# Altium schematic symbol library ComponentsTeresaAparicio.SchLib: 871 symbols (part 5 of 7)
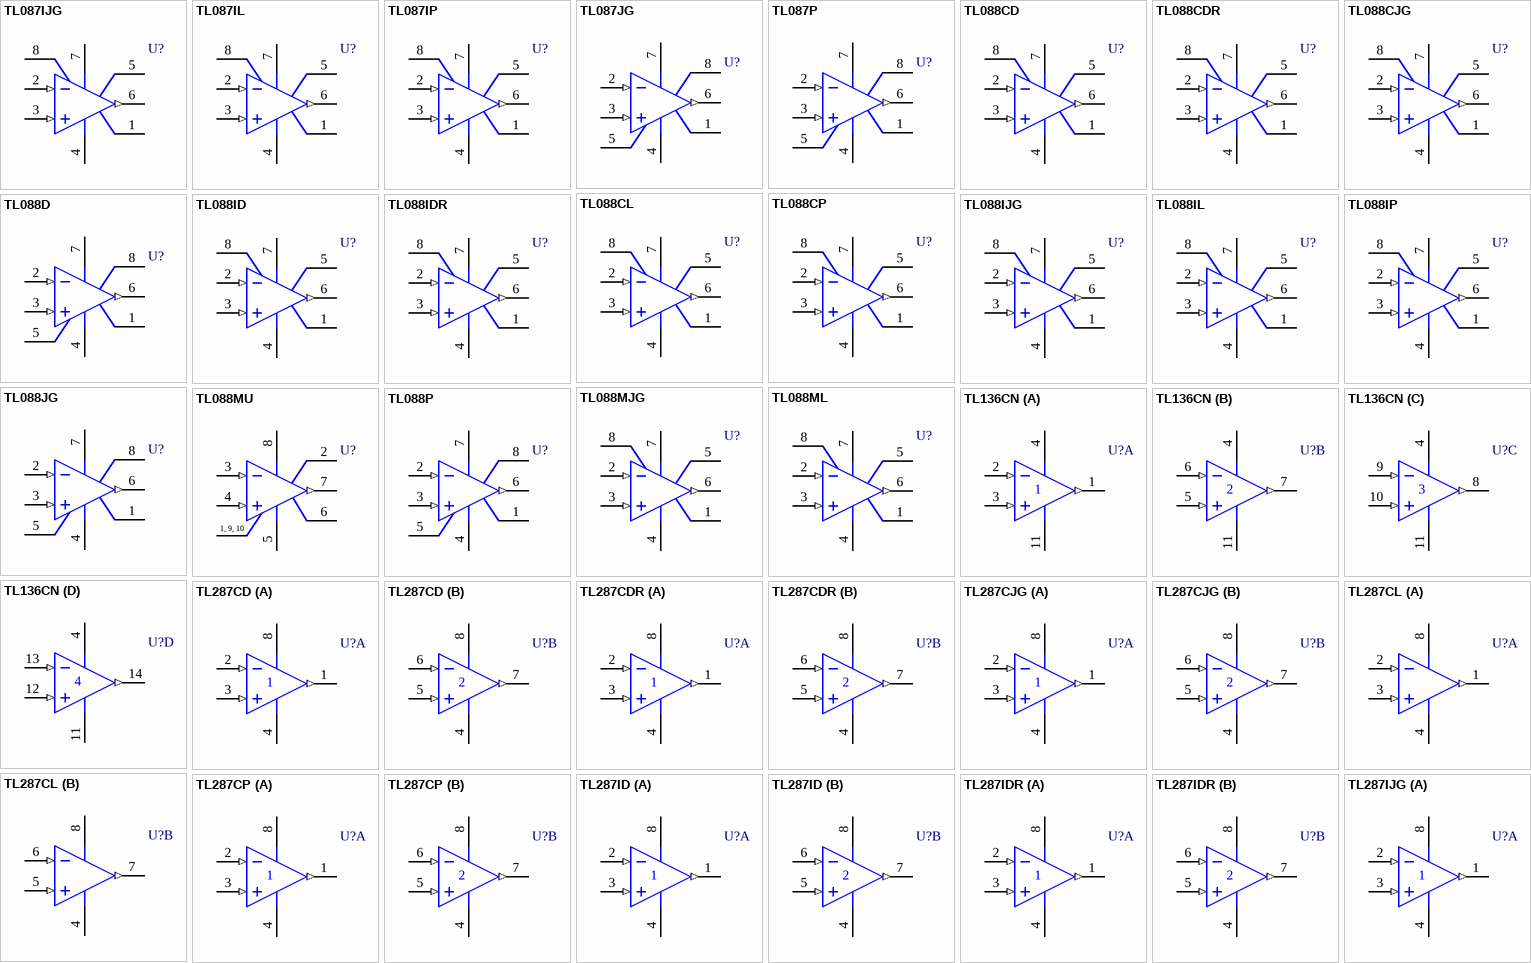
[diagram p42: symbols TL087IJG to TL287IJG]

## TL087IL
designator U?
JFET-Input Operational Amplifier; Note: Pin 4 is in electrical contact with the case; ComponentAvailability: Obsolete
footprint L008 (Can; 8 Leads; Pin Circle Dia. 5.08 mm; Lead Dia. 0.48 mm (max))
pins: 1 OS N1, 2 IN- (in), 3 IN+ (in), 4 V- (power), 5 OS N2, 6 OUT (out), 7 V+ (power), 8 NC

## TL087IP
designator U?
JFET-Input Operational Amplifier; ComponentAvailability: Obsolete
footprint P008 (DIP; 8 Leads; Row Spacing 7.62 mm; Pitch 2.54 mm)
3D model P008 (DIP; 8 Leads; Row Spacing 7.62 mm; Pitch 2.54 mm)
pins: 1 OS N1, 2 IN- (in), 3 IN+ (in), 4 V- (power), 5 OS N2, 6 OUT (out), 7 V+ (power), 8 NC

## TL087JG
designator U?
JFET-Input Operational Amplifier; Note: Pin 8 is not connected
footprint JG008 (DIP; 8 Leads; Row Spacing 7.62 mm; Pitch 2.54 mm)
3D model JG008 (DIP; 8 Leads; Row Spacing 7.62 mm; Pitch 2.54 mm)
simulation model TL087 (SUBCKT)
pins: 1 OS TRIM, 2 IN- (in), 3 IN+ (in), 4 V- (power), 5 OS TRIM, 6 OUT (out), 7 V+ (power), 8 NC

## TL087P
designator U?
JFET-Input Operational Amplifier; Note: Pin 8 is not connected
footprint P008 (DIP; 8 Leads; Row Spacing 7.62 mm; Pitch 2.54 mm)
3D model P008 (DIP; 8 Leads; Row Spacing 7.62 mm; Pitch 2.54 mm)
simulation model TL087 (SUBCKT)
pins: 1 OS TRIM, 2 IN- (in), 3 IN+ (in), 4 V- (power), 5 OS TRIM, 6 OUT (out), 7 V+ (power), 8 NC

## TL088CD
designator U?
JFET-Input Operational Amplifier; ComponentAvailability: Obsolete
footprint D008_L (SOIC, 8-Leads, Body 4.9x3.9mm, Pitch 1.27mm, IPC High Density)
footprint D008_M (SOIC, 8-Leads, Body 4.9x3.9mm, Pitch 1.27mm, IPC Low Density)
footprint D008_M (SOIC, 8-Leads, Body 4.9x3.9mm, Pitch 1.27mm, IPC Low Density)
3D model D008 (8-Pin Small Outline Integrated Circuit 1.27 mm Pitch)
pins: 1 OS N1, 2 IN- (in), 3 IN+ (in), 4 V- (power), 5 OS N2, 6 OUT (out), 7 V+ (power), 8 NC

## TL088CDR
designator U?
JFET-Input Operational Amplifier; ComponentAvailability: Obsolete
footprint D008_L (SOIC, 8-Leads, Body 4.9x3.9mm, Pitch 1.27mm, IPC High Density)
footprint D008_M (SOIC, 8-Leads, Body 4.9x3.9mm, Pitch 1.27mm, IPC Low Density)
footprint D008_M (SOIC, 8-Leads, Body 4.9x3.9mm, Pitch 1.27mm, IPC Low Density)
3D model D008 (8-Pin Small Outline Integrated Circuit 1.27 mm Pitch)
pins: 1 OS N1, 2 IN- (in), 3 IN+ (in), 4 V- (power), 5 OS N2, 6 OUT (out), 7 V+ (power), 8 NC

## TL088CJG
designator U?
JFET-Input Operational Amplifier; ComponentAvailability: Obsolete
footprint JG008 (DIP; 8 Leads; Row Spacing 7.62 mm; Pitch 2.54 mm)
3D model JG008 (DIP; 8 Leads; Row Spacing 7.62 mm; Pitch 2.54 mm)
pins: 1 OS N1, 2 IN- (in), 3 IN+ (in), 4 V- (power), 5 OS N2, 6 OUT (out), 7 V+ (power), 8 NC

## TL088CL
designator U?
JFET-Input Operational Amplifier; Note: Pin 4 is in electrical contact with the case; ComponentAvailability: Obsolete
footprint L008 (Can; 8 Leads; Pin Circle Dia. 5.08 mm; Lead Dia. 0.48 mm (max))
pins: 1 OS N1, 2 IN- (in), 3 IN+ (in), 4 V- (power), 5 OS N2, 6 OUT (out), 7 V+ (power), 8 NC

## TL088CP
designator U?
JFET-Input Operational Amplifier; ComponentAvailability: Obsolete
footprint P008 (DIP; 8 Leads; Row Spacing 7.62 mm; Pitch 2.54 mm)
3D model P008 (DIP; 8 Leads; Row Spacing 7.62 mm; Pitch 2.54 mm)
pins: 1 OS N1, 2 IN- (in), 3 IN+ (in), 4 V- (power), 5 OS N2, 6 OUT (out), 7 V+ (power), 8 NC

## TL088D
designator U?
JFET-Input Operational Amplifier; Note: Pin 8 is not connected
footprint D008_L (SOIC, 8-Leads, Body 4.9x3.9mm, Pitch 1.27mm, IPC High Density)
footprint D008_M (SOIC, 8-Leads, Body 4.9x3.9mm, Pitch 1.27mm, IPC Low Density)
footprint D008_M (SOIC, 8-Leads, Body 4.9x3.9mm, Pitch 1.27mm, IPC Low Density)
3D model D008 (8-Pin Small Outline Integrated Circuit 1.27 mm Pitch)
simulation model TL088 (SUBCKT)
pins: 1 OS TRIM, 2 IN- (in), 3 IN+ (in), 4 V- (power), 5 OS TRIM, 6 OUT (out), 7 V+ (power), 8 NC

## TL088ID
designator U?
JFET-Input Operational Amplifier; ComponentAvailability: Obsolete
footprint D008_L (SOIC, 8-Leads, Body 4.9x3.9mm, Pitch 1.27mm, IPC High Density)
footprint D008_M (SOIC, 8-Leads, Body 4.9x3.9mm, Pitch 1.27mm, IPC Low Density)
footprint D008_M (SOIC, 8-Leads, Body 4.9x3.9mm, Pitch 1.27mm, IPC Low Density)
3D model D008 (8-Pin Small Outline Integrated Circuit 1.27 mm Pitch)
pins: 1 OS N1, 2 IN- (in), 3 IN+ (in), 4 V- (power), 5 OS N2, 6 OUT (out), 7 V+ (power), 8 NC

## TL088IDR
designator U?
JFET-Input Operational Amplifier; ComponentAvailability: Obsolete
footprint D008_L (SOIC, 8-Leads, Body 4.9x3.9mm, Pitch 1.27mm, IPC High Density)
footprint D008_M (SOIC, 8-Leads, Body 4.9x3.9mm, Pitch 1.27mm, IPC Low Density)
footprint D008_M (SOIC, 8-Leads, Body 4.9x3.9mm, Pitch 1.27mm, IPC Low Density)
3D model D008 (8-Pin Small Outline Integrated Circuit 1.27 mm Pitch)
pins: 1 OS N1, 2 IN- (in), 3 IN+ (in), 4 V- (power), 5 OS N2, 6 OUT (out), 7 V+ (power), 8 NC

## TL088IJG
designator U?
JFET-Input Operational Amplifier; ComponentAvailability: Obsolete
footprint JG008 (DIP; 8 Leads; Row Spacing 7.62 mm; Pitch 2.54 mm)
3D model JG008 (DIP; 8 Leads; Row Spacing 7.62 mm; Pitch 2.54 mm)
pins: 1 OS N1, 2 IN- (in), 3 IN+ (in), 4 V- (power), 5 OS N2, 6 OUT (out), 7 V+ (power), 8 NC

## TL088IL
designator U?
JFET-Input Operational Amplifier; Note: Pin 4 is in electrical contact with the case; ComponentAvailability: Obsolete
footprint L008 (Can; 8 Leads; Pin Circle Dia. 5.08 mm; Lead Dia. 0.48 mm (max))
pins: 1 OS N1, 2 IN- (in), 3 IN+ (in), 4 V- (power), 5 OS N2, 6 OUT (out), 7 V+ (power), 8 NC

## TL088IP
designator U?
JFET-Input Operational Amplifier; ComponentAvailability: Obsolete
footprint P008 (DIP; 8 Leads; Row Spacing 7.62 mm; Pitch 2.54 mm)
3D model P008 (DIP; 8 Leads; Row Spacing 7.62 mm; Pitch 2.54 mm)
pins: 1 OS N1, 2 IN- (in), 3 IN+ (in), 4 V- (power), 5 OS N2, 6 OUT (out), 7 V+ (power), 8 NC

## TL088JG
designator U?
JFET-Input Operational Amplifier; Note: Pin 8 is not connected
footprint JG008 (DIP; 8 Leads; Row Spacing 7.62 mm; Pitch 2.54 mm)
3D model JG008 (DIP; 8 Leads; Row Spacing 7.62 mm; Pitch 2.54 mm)
simulation model TL088 (SUBCKT)
pins: 1 OS TRIM, 2 IN- (in), 3 IN+ (in), 4 V- (power), 5 OS TRIM, 6 OUT (out), 7 V+ (power), 8 NC

## TL088MJG
designator U?
JFET-Input Operational Amplifier; ComponentAvailability: Obsolete
footprint JG008 (DIP; 8 Leads; Row Spacing 7.62 mm; Pitch 2.54 mm)
3D model JG008 (DIP; 8 Leads; Row Spacing 7.62 mm; Pitch 2.54 mm)
pins: 1 OS N1, 2 IN- (in), 3 IN+ (in), 4 V- (power), 5 OS N2, 6 OUT (out), 7 V+ (power), 8 NC

## TL088ML
designator U?
JFET-Input Operational Amplifier; Note: Pin 4 is in electrical contact with the case; ComponentAvailability: Obsolete
footprint L008 (Can; 8 Leads; Pin Circle Dia. 5.08 mm; Lead Dia. 0.48 mm (max))
pins: 1 OS N1, 2 IN- (in), 3 IN+ (in), 4 V- (power), 5 OS N2, 6 OUT (out), 7 V+ (power), 8 NC

## TL088MU
designator U?
JFET-Input Operational Amplifier; ComponentAvailability: Obsolete
footprint U010 (DFP; 10 Leads; Body 7.1 x 6.4 mm (LxW max); Pitch 1.27 mm)
3D model U010 (DFP; 10 Leads; Body 7.1 x 6.4 mm (LxW max); Pitch 1.27 mm)
pins: 1 NC, 2 OS N1, 3 IN- (in), 4 IN+ (in), 5 V- (power), 6 OS N2, 7 OUT (out), 8 V+ (power), 9 NC, 10 NC

## TL088P
designator U?
JFET-Input Operational Amplifier; Note: Pin 8 is not connected
footprint P008 (DIP; 8 Leads; Row Spacing 7.62 mm; Pitch 2.54 mm)
3D model P008 (DIP; 8 Leads; Row Spacing 7.62 mm; Pitch 2.54 mm)
simulation model TL088 (SUBCKT)
pins: 1 OS TRIM, 2 IN- (in), 3 IN+ (in), 4 V- (power), 5 OS TRIM, 6 OUT (out), 7 V+ (power), 8 NC

## TL136CN
designator U?
Quad High-Performance Operational Amplifier
footprint N014 (DIP; 14 Leads; Row Spacing 7.62 mm; Pitch 2.54 mm)
3D model N014 (DIP; 14 Leads; Row Spacing 7.62 mm; Pitch 2.54 mm)
pins on every part: 4 V+ (power), 11 V- (power)
part A pins: 1 OUT (out), 2 IN- (in), 3 IN+ (in)
part B pins: 5 IN+ (in), 6 IN- (in), 7 OUT (out)
part C pins: 8 OUT (out), 9 IN- (in), 10 IN+ (in)
part D pins: 12 IN+ (in), 13 IN- (in), 14 OUT (out)

## TL287CD
designator U?
JFET-Input Operational Amplifier; ComponentAvailability: Obsolete
footprint D008_L (SOIC, 8-Leads, Body 4.9x3.9mm, Pitch 1.27mm, IPC High Density)
footprint D008_M (SOIC, 8-Leads, Body 4.9x3.9mm, Pitch 1.27mm, IPC Low Density)
footprint D008_M (SOIC, 8-Leads, Body 4.9x3.9mm, Pitch 1.27mm, IPC Low Density)
3D model D008 (8-Pin Small Outline Integrated Circuit 1.27 mm Pitch)
pins on every part: 4 V- (power), 8 V+ (power)
part A pins: 1 OUT (out), 2 IN- (in), 3 IN+ (in)
part B pins: 5 IN+ (in), 6 IN- (in), 7 OUT (out)

## TL287CDR
designator U?
JFET-Input Operational Amplifier; ComponentAvailability: Obsolete
footprint D008_L (SOIC, 8-Leads, Body 4.9x3.9mm, Pitch 1.27mm, IPC High Density)
footprint D008_M (SOIC, 8-Leads, Body 4.9x3.9mm, Pitch 1.27mm, IPC Low Density)
footprint D008_M (SOIC, 8-Leads, Body 4.9x3.9mm, Pitch 1.27mm, IPC Low Density)
3D model D008 (8-Pin Small Outline Integrated Circuit 1.27 mm Pitch)
pins on every part: 4 V- (power), 8 V+ (power)
part A pins: 1 OUT (out), 2 IN- (in), 3 IN+ (in)
part B pins: 5 IN+ (in), 6 IN- (in), 7 OUT (out)

## TL287CJG
designator U?
JFET-Input Operational Amplifier; ComponentAvailability: Obsolete
footprint JG008 (DIP; 8 Leads; Row Spacing 7.62 mm; Pitch 2.54 mm)
3D model JG008 (DIP; 8 Leads; Row Spacing 7.62 mm; Pitch 2.54 mm)
pins on every part: 4 V- (power), 8 V+ (power)
part A pins: 1 OUT (out), 2 IN- (in), 3 IN+ (in)
part B pins: 5 IN+ (in), 6 IN- (in), 7 OUT (out)

## TL287CL
designator U?
JFET-Input Operational Amplifier; Note: Pin 4 is in electrical contact with the case; ComponentAvailability: Obsolete
footprint L008 (Can; 8 Leads; Pin Circle Dia. 5.08 mm; Lead Dia. 0.48 mm (max))
pins on every part: 4 V- (power), 8 V+ (power)
part A pins: 1 OUT (out), 2 IN- (in), 3 IN+ (in)
part B pins: 5 IN+ (in), 6 IN- (in), 7 OUT (out)

## TL287CP
designator U?
JFET-Input Operational Amplifier; ComponentAvailability: Obsolete
footprint P008 (DIP; 8 Leads; Row Spacing 7.62 mm; Pitch 2.54 mm)
3D model P008 (DIP; 8 Leads; Row Spacing 7.62 mm; Pitch 2.54 mm)
pins on every part: 4 V- (power), 8 V+ (power)
part A pins: 1 OUT (out), 2 IN- (in), 3 IN+ (in)
part B pins: 5 IN+ (in), 6 IN- (in), 7 OUT (out)

## TL287ID
designator U?
JFET-Input Operational Amplifier; ComponentAvailability: Obsolete
footprint D008_L (SOIC, 8-Leads, Body 4.9x3.9mm, Pitch 1.27mm, IPC High Density)
footprint D008_M (SOIC, 8-Leads, Body 4.9x3.9mm, Pitch 1.27mm, IPC Low Density)
footprint D008_M (SOIC, 8-Leads, Body 4.9x3.9mm, Pitch 1.27mm, IPC Low Density)
3D model D008 (8-Pin Small Outline Integrated Circuit 1.27 mm Pitch)
pins on every part: 4 V- (power), 8 V+ (power)
part A pins: 1 OUT (out), 2 IN- (in), 3 IN+ (in)
part B pins: 5 IN+ (in), 6 IN- (in), 7 OUT (out)

## TL287IDR
designator U?
JFET-Input Operational Amplifier; ComponentAvailability: Obsolete
footprint D008_L (SOIC, 8-Leads, Body 4.9x3.9mm, Pitch 1.27mm, IPC High Density)
footprint D008_M (SOIC, 8-Leads, Body 4.9x3.9mm, Pitch 1.27mm, IPC Low Density)
footprint D008_M (SOIC, 8-Leads, Body 4.9x3.9mm, Pitch 1.27mm, IPC Low Density)
3D model D008 (8-Pin Small Outline Integrated Circuit 1.27 mm Pitch)
pins on every part: 4 V- (power), 8 V+ (power)
part A pins: 1 OUT (out), 2 IN- (in), 3 IN+ (in)
part B pins: 5 IN+ (in), 6 IN- (in), 7 OUT (out)

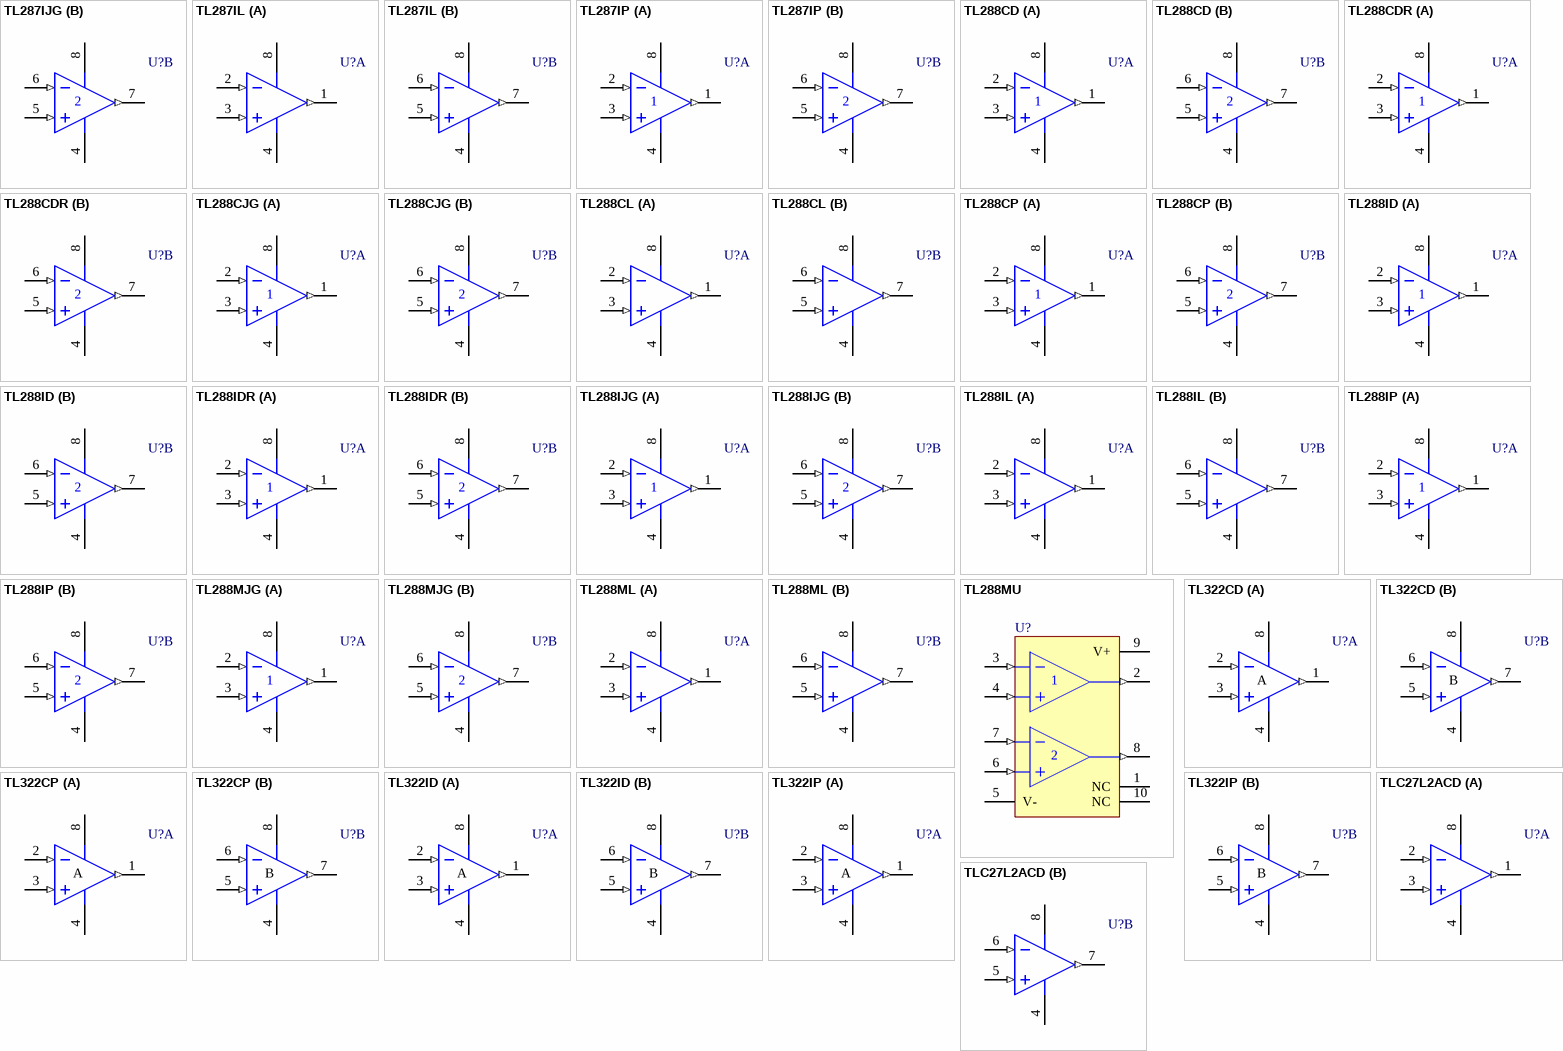
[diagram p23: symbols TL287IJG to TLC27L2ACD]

## TL287IJG
designator U?
JFET-Input Operational Amplifier; ComponentAvailability: Obsolete
footprint JG008 (DIP; 8 Leads; Row Spacing 7.62 mm; Pitch 2.54 mm)
3D model JG008 (DIP; 8 Leads; Row Spacing 7.62 mm; Pitch 2.54 mm)
pins on every part: 4 V- (power), 8 V+ (power)
part A pins: 1 OUT (out), 2 IN- (in), 3 IN+ (in)
part B pins: 5 IN+ (in), 6 IN- (in), 7 OUT (out)

## TL287IL
designator U?
JFET-Input Operational Amplifier; Note: Pin 4 is in electrical contact with the case; ComponentAvailability: Obsolete
footprint L008 (Can; 8 Leads; Pin Circle Dia. 5.08 mm; Lead Dia. 0.48 mm (max))
pins on every part: 4 V- (power), 8 V+ (power)
part A pins: 1 OUT (out), 2 IN- (in), 3 IN+ (in)
part B pins: 5 IN+ (in), 6 IN- (in), 7 OUT (out)

## TL287IP
designator U?
JFET-Input Operational Amplifier; ComponentAvailability: Obsolete
footprint P008 (DIP; 8 Leads; Row Spacing 7.62 mm; Pitch 2.54 mm)
3D model P008 (DIP; 8 Leads; Row Spacing 7.62 mm; Pitch 2.54 mm)
pins on every part: 4 V- (power), 8 V+ (power)
part A pins: 1 OUT (out), 2 IN- (in), 3 IN+ (in)
part B pins: 5 IN+ (in), 6 IN- (in), 7 OUT (out)

## TL288CD
designator U?
JFET-Input Operational Amplifier
footprint D008_L (SOIC, 8-Leads, Body 4.9x3.9mm, Pitch 1.27mm, IPC High Density)
footprint D008_M (SOIC, 8-Leads, Body 4.9x3.9mm, Pitch 1.27mm, IPC Low Density)
footprint D008_M (SOIC, 8-Leads, Body 4.9x3.9mm, Pitch 1.27mm, IPC Low Density)
3D model D008 (8-Pin Small Outline Integrated Circuit 1.27 mm Pitch)
pins on every part: 4 V- (power), 8 V+ (power)
part A pins: 1 OUT (out), 2 IN- (in), 3 IN+ (in)
part B pins: 5 IN+ (in), 6 IN- (in), 7 OUT (out)

## TL288CDR
designator U?
JFET-Input Operational Amplifier
footprint D008_L (SOIC, 8-Leads, Body 4.9x3.9mm, Pitch 1.27mm, IPC High Density)
footprint D008_M (SOIC, 8-Leads, Body 4.9x3.9mm, Pitch 1.27mm, IPC Low Density)
footprint D008_M (SOIC, 8-Leads, Body 4.9x3.9mm, Pitch 1.27mm, IPC Low Density)
3D model D008 (8-Pin Small Outline Integrated Circuit 1.27 mm Pitch)
pins on every part: 4 V- (power), 8 V+ (power)
part A pins: 1 OUT (out), 2 IN- (in), 3 IN+ (in)
part B pins: 5 IN+ (in), 6 IN- (in), 7 OUT (out)

## TL288CJG
designator U?
JFET-Input Operational Amplifier
footprint JG008 (DIP; 8 Leads; Row Spacing 7.62 mm; Pitch 2.54 mm)
3D model JG008 (DIP; 8 Leads; Row Spacing 7.62 mm; Pitch 2.54 mm)
pins on every part: 4 V- (power), 8 V+ (power)
part A pins: 1 OUT (out), 2 IN- (in), 3 IN+ (in)
part B pins: 5 IN+ (in), 6 IN- (in), 7 OUT (out)

## TL288CL
designator U?
JFET-Input Operational Amplifier; Note: Pin 4 is in electrical contact with the case
footprint L008 (Can; 8 Leads; Pin Circle Dia. 5.08 mm; Lead Dia. 0.48 mm (max))
pins on every part: 4 V- (power), 8 V+ (power)
part A pins: 1 OUT (out), 2 IN- (in), 3 IN+ (in)
part B pins: 5 IN+ (in), 6 IN- (in), 7 OUT (out)

## TL288CP
designator U?
JFET-Input Operational Amplifier
footprint P008 (DIP; 8 Leads; Row Spacing 7.62 mm; Pitch 2.54 mm)
3D model P008 (DIP; 8 Leads; Row Spacing 7.62 mm; Pitch 2.54 mm)
pins on every part: 4 V- (power), 8 V+ (power)
part A pins: 1 OUT (out), 2 IN- (in), 3 IN+ (in)
part B pins: 5 IN+ (in), 6 IN- (in), 7 OUT (out)

## TL288ID
designator U?
JFET-Input Operational Amplifier
footprint D008_L (SOIC, 8-Leads, Body 4.9x3.9mm, Pitch 1.27mm, IPC High Density)
footprint D008_M (SOIC, 8-Leads, Body 4.9x3.9mm, Pitch 1.27mm, IPC Low Density)
footprint D008_M (SOIC, 8-Leads, Body 4.9x3.9mm, Pitch 1.27mm, IPC Low Density)
3D model D008 (8-Pin Small Outline Integrated Circuit 1.27 mm Pitch)
pins on every part: 4 V- (power), 8 V+ (power)
part A pins: 1 OUT (out), 2 IN- (in), 3 IN+ (in)
part B pins: 5 IN+ (in), 6 IN- (in), 7 OUT (out)

## TL288IDR
designator U?
JFET-Input Operational Amplifier
footprint D008_L (SOIC, 8-Leads, Body 4.9x3.9mm, Pitch 1.27mm, IPC High Density)
footprint D008_M (SOIC, 8-Leads, Body 4.9x3.9mm, Pitch 1.27mm, IPC Low Density)
footprint D008_M (SOIC, 8-Leads, Body 4.9x3.9mm, Pitch 1.27mm, IPC Low Density)
3D model D008 (8-Pin Small Outline Integrated Circuit 1.27 mm Pitch)
pins on every part: 4 V- (power), 8 V+ (power)
part A pins: 1 OUT (out), 2 IN- (in), 3 IN+ (in)
part B pins: 5 IN+ (in), 6 IN- (in), 7 OUT (out)

## TL288IJG
designator U?
JFET-Input Operational Amplifier
footprint JG008 (DIP; 8 Leads; Row Spacing 7.62 mm; Pitch 2.54 mm)
3D model JG008 (DIP; 8 Leads; Row Spacing 7.62 mm; Pitch 2.54 mm)
pins on every part: 4 V- (power), 8 V+ (power)
part A pins: 1 OUT (out), 2 IN- (in), 3 IN+ (in)
part B pins: 5 IN+ (in), 6 IN- (in), 7 OUT (out)

## TL288IL
designator U?
JFET-Input Operational Amplifier; Note: Pin 4 is in electrical contact with the case
footprint L008 (Can; 8 Leads; Pin Circle Dia. 5.08 mm; Lead Dia. 0.48 mm (max))
pins on every part: 4 V- (power), 8 V+ (power)
part A pins: 1 OUT (out), 2 IN- (in), 3 IN+ (in)
part B pins: 5 IN+ (in), 6 IN- (in), 7 OUT (out)

## TL288IP
designator U?
JFET-Input Operational Amplifier
footprint P008 (DIP; 8 Leads; Row Spacing 7.62 mm; Pitch 2.54 mm)
3D model P008 (DIP; 8 Leads; Row Spacing 7.62 mm; Pitch 2.54 mm)
pins on every part: 4 V- (power), 8 V+ (power)
part A pins: 1 OUT (out), 2 IN- (in), 3 IN+ (in)
part B pins: 5 IN+ (in), 6 IN- (in), 7 OUT (out)

## TL288MJG
designator U?
JFET-Input Operational Amplifier
footprint JG008 (DIP; 8 Leads; Row Spacing 7.62 mm; Pitch 2.54 mm)
3D model JG008 (DIP; 8 Leads; Row Spacing 7.62 mm; Pitch 2.54 mm)
pins on every part: 4 V- (power), 8 V+ (power)
part A pins: 1 OUT (out), 2 IN- (in), 3 IN+ (in)
part B pins: 5 IN+ (in), 6 IN- (in), 7 OUT (out)

## TL288ML
designator U?
JFET-Input Operational Amplifier; Note: Pin 4 is in electrical contact with the case
footprint L008 (Can; 8 Leads; Pin Circle Dia. 5.08 mm; Lead Dia. 0.48 mm (max))
pins on every part: 4 V- (power), 8 V+ (power)
part A pins: 1 OUT (out), 2 IN- (in), 3 IN+ (in)
part B pins: 5 IN+ (in), 6 IN- (in), 7 OUT (out)

## TL288MU
designator U?
JFET-Input Operational Amplifier; ComponentAvailability: Obsolete
footprint U010 (DFP; 10 Leads; Body 7.1 x 6.4 mm (LxW max); Pitch 1.27 mm)
3D model U010 (DFP; 10 Leads; Body 7.1 x 6.4 mm (LxW max); Pitch 1.27 mm)
pins: 1 NC, 2 OUT (out), 3 IN- (in), 4 IN+ (in), 5 V- (power), 6 IN+ (in), 7 IN- (in), 8 OUT (out), 9 V+ (power), 10 NC

## TL322CD
designator U?
Dual Low-Power Operational Amplifier
footprint D008_L (SOIC, 8-Leads, Body 4.9x3.9mm, Pitch 1.27mm, IPC High Density)
footprint D008_M (SOIC, 8-Leads, Body 4.9x3.9mm, Pitch 1.27mm, IPC Low Density)
footprint D008_M (SOIC, 8-Leads, Body 4.9x3.9mm, Pitch 1.27mm, IPC Low Density)
3D model D008 (8-Pin Small Outline Integrated Circuit 1.27 mm Pitch)
simulation model TL322 (SUBCKT)
pins on every part: 4 V- (power), 8 V+ (power)
part A pins: 1 OUT (out), 2 IN- (in), 3 IN+ (in)
part B pins: 5 IN+ (in), 6 IN- (in), 7 OUT (out)

## TL322CP
designator U?
Dual Low-Power Operational Amplifier; ComponentAvailability: Obsolete
footprint P008 (DIP; 8 Leads; Row Spacing 7.62 mm; Pitch 2.54 mm)
3D model P008 (DIP; 8 Leads; Row Spacing 7.62 mm; Pitch 2.54 mm)
simulation model TL322 (SUBCKT)
pins on every part: 4 V- (power), 8 V+ (power)
part A pins: 1 OUT (out), 2 IN- (in), 3 IN+ (in)
part B pins: 5 IN+ (in), 6 IN- (in), 7 OUT (out)

## TL322ID
designator U?
Dual Low-Power Operational Amplifier; ComponentAvailability: Obsolete
footprint D008_L (SOIC, 8-Leads, Body 4.9x3.9mm, Pitch 1.27mm, IPC High Density)
footprint D008_M (SOIC, 8-Leads, Body 4.9x3.9mm, Pitch 1.27mm, IPC Low Density)
footprint D008_M (SOIC, 8-Leads, Body 4.9x3.9mm, Pitch 1.27mm, IPC Low Density)
3D model D008 (8-Pin Small Outline Integrated Circuit 1.27 mm Pitch)
simulation model TL322 (SUBCKT)
pins on every part: 4 V- (power), 8 V+ (power)
part A pins: 1 OUT (out), 2 IN- (in), 3 IN+ (in)
part B pins: 5 IN+ (in), 6 IN- (in), 7 OUT (out)

## TL322IP
designator U?
Dual Low-Power Operational Amplifier; ComponentAvailability: Obsolete
footprint P008 (DIP; 8 Leads; Row Spacing 7.62 mm; Pitch 2.54 mm)
3D model P008 (DIP; 8 Leads; Row Spacing 7.62 mm; Pitch 2.54 mm)
simulation model TL322 (SUBCKT)
pins on every part: 4 V- (power), 8 V+ (power)
part A pins: 1 OUT (out), 2 IN- (in), 3 IN+ (in)
part B pins: 5 IN+ (in), 6 IN- (in), 7 OUT (out)

## TLC27L2ACD
designator U?
LinCMOS Precision Dual Operational Amplifier
footprint D008_L (SOIC, 8-Leads, Body 4.9x3.9mm, Pitch 1.27mm, IPC High Density)
footprint D008_M (SOIC, 8-Leads, Body 4.9x3.9mm, Pitch 1.27mm, IPC Low Density)
footprint D008_M (SOIC, 8-Leads, Body 4.9x3.9mm, Pitch 1.27mm, IPC Low Density)
3D model D008 (8-Pin Small Outline Integrated Circuit 1.27 mm Pitch)
pins on every part: 4 GND (power), 8 VDD (power)
part A pins: 1 OUT (out), 2 IN- (in), 3 IN+ (in)
part B pins: 5 IN+ (in), 6 IN- (in), 7 OUT (out)

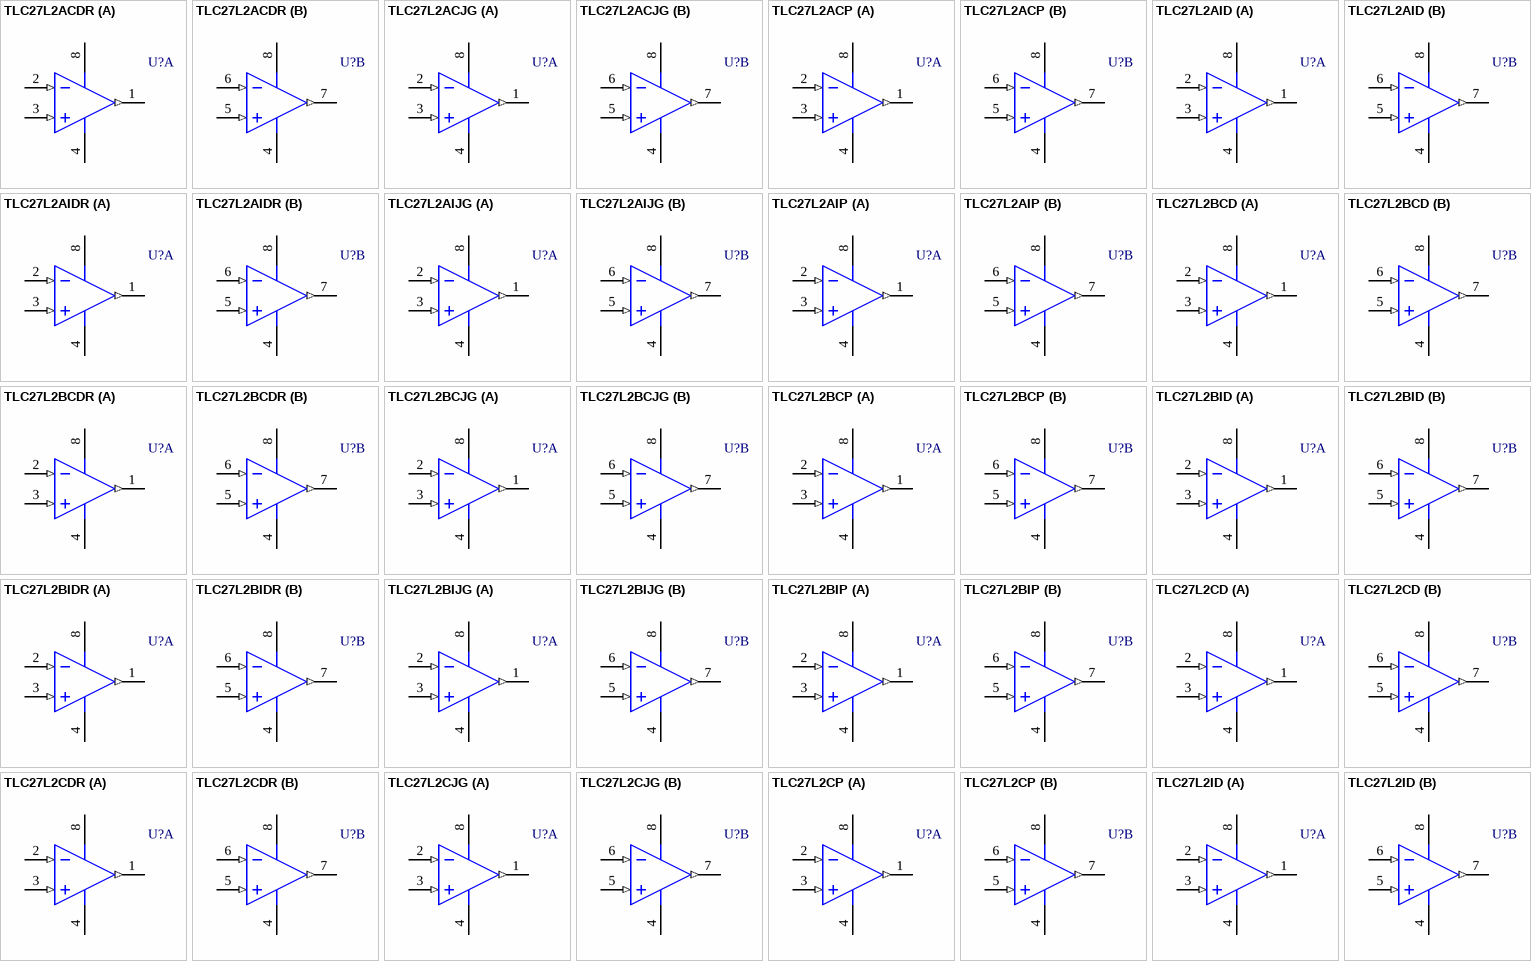
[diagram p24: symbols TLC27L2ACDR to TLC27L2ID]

## TLC27L2ACDR
designator U?
LinCMOS Precision Dual Operational Amplifier
footprint D008_L (SOIC, 8-Leads, Body 4.9x3.9mm, Pitch 1.27mm, IPC High Density)
footprint D008_M (SOIC, 8-Leads, Body 4.9x3.9mm, Pitch 1.27mm, IPC Low Density)
footprint D008_M (SOIC, 8-Leads, Body 4.9x3.9mm, Pitch 1.27mm, IPC Low Density)
3D model D008 (8-Pin Small Outline Integrated Circuit 1.27 mm Pitch)
pins on every part: 4 GND (power), 8 VDD (power)
part A pins: 1 OUT (out), 2 IN- (in), 3 IN+ (in)
part B pins: 5 IN+ (in), 6 IN- (in), 7 OUT (out)

## TLC27L2ACJG
designator U?
LinCMOS Precision Dual Operational Amplifier
footprint JG008 (DIP; 8 Leads; Row Spacing 7.62 mm; Pitch 2.54 mm)
3D model JG008 (DIP; 8 Leads; Row Spacing 7.62 mm; Pitch 2.54 mm)
pins on every part: 4 GND (power), 8 VDD (power)
part A pins: 1 OUT (out), 2 IN- (in), 3 IN+ (in)
part B pins: 5 IN+ (in), 6 IN- (in), 7 OUT (out)

## TLC27L2ACP
designator U?
LinCMOS Precision Dual Operational Amplifier
footprint P008 (DIP; 8 Leads; Row Spacing 7.62 mm; Pitch 2.54 mm)
3D model P008 (DIP; 8 Leads; Row Spacing 7.62 mm; Pitch 2.54 mm)
pins on every part: 4 GND (power), 8 VDD (power)
part A pins: 1 OUT (out), 2 IN- (in), 3 IN+ (in)
part B pins: 5 IN+ (in), 6 IN- (in), 7 OUT (out)

## TLC27L2AID
designator U?
LinCMOS Precision Dual Operational Amplifier
footprint D008_L (SOIC, 8-Leads, Body 4.9x3.9mm, Pitch 1.27mm, IPC High Density)
footprint D008_M (SOIC, 8-Leads, Body 4.9x3.9mm, Pitch 1.27mm, IPC Low Density)
footprint D008_M (SOIC, 8-Leads, Body 4.9x3.9mm, Pitch 1.27mm, IPC Low Density)
3D model D008 (8-Pin Small Outline Integrated Circuit 1.27 mm Pitch)
pins on every part: 4 GND (power), 8 VDD (power)
part A pins: 1 OUT (out), 2 IN- (in), 3 IN+ (in)
part B pins: 5 IN+ (in), 6 IN- (in), 7 OUT (out)

## TLC27L2AIDR
designator U?
LinCMOS Precision Dual Operational Amplifier
footprint D008_L (SOIC, 8-Leads, Body 4.9x3.9mm, Pitch 1.27mm, IPC High Density)
footprint D008_M (SOIC, 8-Leads, Body 4.9x3.9mm, Pitch 1.27mm, IPC Low Density)
footprint D008_M (SOIC, 8-Leads, Body 4.9x3.9mm, Pitch 1.27mm, IPC Low Density)
3D model D008 (8-Pin Small Outline Integrated Circuit 1.27 mm Pitch)
pins on every part: 4 GND (power), 8 VDD (power)
part A pins: 1 OUT (out), 2 IN- (in), 3 IN+ (in)
part B pins: 5 IN+ (in), 6 IN- (in), 7 OUT (out)

## TLC27L2AIJG
designator U?
LinCMOS Precision Dual Operational Amplifier
footprint JG008 (DIP; 8 Leads; Row Spacing 7.62 mm; Pitch 2.54 mm)
3D model JG008 (DIP; 8 Leads; Row Spacing 7.62 mm; Pitch 2.54 mm)
pins on every part: 4 GND (power), 8 VDD (power)
part A pins: 1 OUT (out), 2 IN- (in), 3 IN+ (in)
part B pins: 5 IN+ (in), 6 IN- (in), 7 OUT (out)

## TLC27L2AIP
designator U?
LinCMOS Precision Dual Operational Amplifier
footprint P008 (DIP; 8 Leads; Row Spacing 7.62 mm; Pitch 2.54 mm)
3D model P008 (DIP; 8 Leads; Row Spacing 7.62 mm; Pitch 2.54 mm)
pins on every part: 4 GND (power), 8 VDD (power)
part A pins: 1 OUT (out), 2 IN- (in), 3 IN+ (in)
part B pins: 5 IN+ (in), 6 IN- (in), 7 OUT (out)

## TLC27L2BCD
designator U?
LinCMOS Precision Dual Operational Amplifier
footprint D008_L (SOIC, 8-Leads, Body 4.9x3.9mm, Pitch 1.27mm, IPC High Density)
footprint D008_M (SOIC, 8-Leads, Body 4.9x3.9mm, Pitch 1.27mm, IPC Low Density)
footprint D008_M (SOIC, 8-Leads, Body 4.9x3.9mm, Pitch 1.27mm, IPC Low Density)
3D model D008 (8-Pin Small Outline Integrated Circuit 1.27 mm Pitch)
pins on every part: 4 GND (power), 8 VDD (power)
part A pins: 1 OUT (out), 2 IN- (in), 3 IN+ (in)
part B pins: 5 IN+ (in), 6 IN- (in), 7 OUT (out)

## TLC27L2BCDR
designator U?
LinCMOS Precision Dual Operational Amplifier
footprint D008_L (SOIC, 8-Leads, Body 4.9x3.9mm, Pitch 1.27mm, IPC High Density)
footprint D008_M (SOIC, 8-Leads, Body 4.9x3.9mm, Pitch 1.27mm, IPC Low Density)
footprint D008_M (SOIC, 8-Leads, Body 4.9x3.9mm, Pitch 1.27mm, IPC Low Density)
3D model D008 (8-Pin Small Outline Integrated Circuit 1.27 mm Pitch)
pins on every part: 4 GND (power), 8 VDD (power)
part A pins: 1 OUT (out), 2 IN- (in), 3 IN+ (in)
part B pins: 5 IN+ (in), 6 IN- (in), 7 OUT (out)

## TLC27L2BCJG
designator U?
LinCMOS Precision Dual Operational Amplifier
footprint JG008 (DIP; 8 Leads; Row Spacing 7.62 mm; Pitch 2.54 mm)
3D model JG008 (DIP; 8 Leads; Row Spacing 7.62 mm; Pitch 2.54 mm)
pins on every part: 4 GND (power), 8 VDD (power)
part A pins: 1 OUT (out), 2 IN- (in), 3 IN+ (in)
part B pins: 5 IN+ (in), 6 IN- (in), 7 OUT (out)

## TLC27L2BCP
designator U?
LinCMOS Precision Dual Operational Amplifier
footprint P008 (DIP; 8 Leads; Row Spacing 7.62 mm; Pitch 2.54 mm)
3D model P008 (DIP; 8 Leads; Row Spacing 7.62 mm; Pitch 2.54 mm)
pins on every part: 4 GND (power), 8 VDD (power)
part A pins: 1 OUT (out), 2 IN- (in), 3 IN+ (in)
part B pins: 5 IN+ (in), 6 IN- (in), 7 OUT (out)

## TLC27L2BID
designator U?
LinCMOS Precision Dual Operational Amplifier
footprint D008_L (SOIC, 8-Leads, Body 4.9x3.9mm, Pitch 1.27mm, IPC High Density)
footprint D008_M (SOIC, 8-Leads, Body 4.9x3.9mm, Pitch 1.27mm, IPC Low Density)
footprint D008_M (SOIC, 8-Leads, Body 4.9x3.9mm, Pitch 1.27mm, IPC Low Density)
3D model D008 (8-Pin Small Outline Integrated Circuit 1.27 mm Pitch)
pins on every part: 4 GND (power), 8 VDD (power)
part A pins: 1 OUT (out), 2 IN- (in), 3 IN+ (in)
part B pins: 5 IN+ (in), 6 IN- (in), 7 OUT (out)

## TLC27L2BIDR
designator U?
LinCMOS Precision Dual Operational Amplifier
footprint D008_L (SOIC, 8-Leads, Body 4.9x3.9mm, Pitch 1.27mm, IPC High Density)
footprint D008_M (SOIC, 8-Leads, Body 4.9x3.9mm, Pitch 1.27mm, IPC Low Density)
footprint D008_M (SOIC, 8-Leads, Body 4.9x3.9mm, Pitch 1.27mm, IPC Low Density)
3D model D008 (8-Pin Small Outline Integrated Circuit 1.27 mm Pitch)
pins on every part: 4 GND (power), 8 VDD (power)
part A pins: 1 OUT (out), 2 IN- (in), 3 IN+ (in)
part B pins: 5 IN+ (in), 6 IN- (in), 7 OUT (out)

## TLC27L2BIJG
designator U?
LinCMOS Precision Dual Operational Amplifier
footprint JG008 (DIP; 8 Leads; Row Spacing 7.62 mm; Pitch 2.54 mm)
3D model JG008 (DIP; 8 Leads; Row Spacing 7.62 mm; Pitch 2.54 mm)
pins on every part: 4 GND (power), 8 VDD (power)
part A pins: 1 OUT (out), 2 IN- (in), 3 IN+ (in)
part B pins: 5 IN+ (in), 6 IN- (in), 7 OUT (out)

## TLC27L2BIP
designator U?
LinCMOS Precision Dual Operational Amplifier
footprint P008 (DIP; 8 Leads; Row Spacing 7.62 mm; Pitch 2.54 mm)
3D model P008 (DIP; 8 Leads; Row Spacing 7.62 mm; Pitch 2.54 mm)
pins on every part: 4 GND (power), 8 VDD (power)
part A pins: 1 OUT (out), 2 IN- (in), 3 IN+ (in)
part B pins: 5 IN+ (in), 6 IN- (in), 7 OUT (out)

## TLC27L2CD
designator U?
LinCMOS Precision Dual Operational Amplifier
footprint D008_L (SOIC, 8-Leads, Body 4.9x3.9mm, Pitch 1.27mm, IPC High Density)
footprint D008_M (SOIC, 8-Leads, Body 4.9x3.9mm, Pitch 1.27mm, IPC Low Density)
footprint D008_M (SOIC, 8-Leads, Body 4.9x3.9mm, Pitch 1.27mm, IPC Low Density)
3D model D008 (8-Pin Small Outline Integrated Circuit 1.27 mm Pitch)
pins on every part: 4 GND (power), 8 VDD (power)
part A pins: 1 OUT (out), 2 IN- (in), 3 IN+ (in)
part B pins: 5 IN+ (in), 6 IN- (in), 7 OUT (out)

## TLC27L2CDR
designator U?
LinCMOS Precision Dual Operational Amplifier
footprint D008_L (SOIC, 8-Leads, Body 4.9x3.9mm, Pitch 1.27mm, IPC High Density)
footprint D008_M (SOIC, 8-Leads, Body 4.9x3.9mm, Pitch 1.27mm, IPC Low Density)
footprint D008_M (SOIC, 8-Leads, Body 4.9x3.9mm, Pitch 1.27mm, IPC Low Density)
3D model D008 (8-Pin Small Outline Integrated Circuit 1.27 mm Pitch)
pins on every part: 4 GND (power), 8 VDD (power)
part A pins: 1 OUT (out), 2 IN- (in), 3 IN+ (in)
part B pins: 5 IN+ (in), 6 IN- (in), 7 OUT (out)

## TLC27L2CJG
designator U?
LinCMOS Precision Dual Operational Amplifier
footprint JG008 (DIP; 8 Leads; Row Spacing 7.62 mm; Pitch 2.54 mm)
3D model JG008 (DIP; 8 Leads; Row Spacing 7.62 mm; Pitch 2.54 mm)
pins on every part: 4 GND (power), 8 VDD (power)
part A pins: 1 OUT (out), 2 IN- (in), 3 IN+ (in)
part B pins: 5 IN+ (in), 6 IN- (in), 7 OUT (out)

## TLC27L2CP
designator U?
LinCMOS Precision Dual Operational Amplifier
footprint P008 (DIP; 8 Leads; Row Spacing 7.62 mm; Pitch 2.54 mm)
3D model P008 (DIP; 8 Leads; Row Spacing 7.62 mm; Pitch 2.54 mm)
pins on every part: 4 GND (power), 8 VDD (power)
part A pins: 1 OUT (out), 2 IN- (in), 3 IN+ (in)
part B pins: 5 IN+ (in), 6 IN- (in), 7 OUT (out)

## TLC27L2ID
designator U?
LinCMOS Precision Dual Operational Amplifier
footprint D008_L (SOIC, 8-Leads, Body 4.9x3.9mm, Pitch 1.27mm, IPC High Density)
footprint D008_M (SOIC, 8-Leads, Body 4.9x3.9mm, Pitch 1.27mm, IPC Low Density)
footprint D008_M (SOIC, 8-Leads, Body 4.9x3.9mm, Pitch 1.27mm, IPC Low Density)
3D model D008 (8-Pin Small Outline Integrated Circuit 1.27 mm Pitch)
pins on every part: 4 GND (power), 8 VDD (power)
part A pins: 1 OUT (out), 2 IN- (in), 3 IN+ (in)
part B pins: 5 IN+ (in), 6 IN- (in), 7 OUT (out)

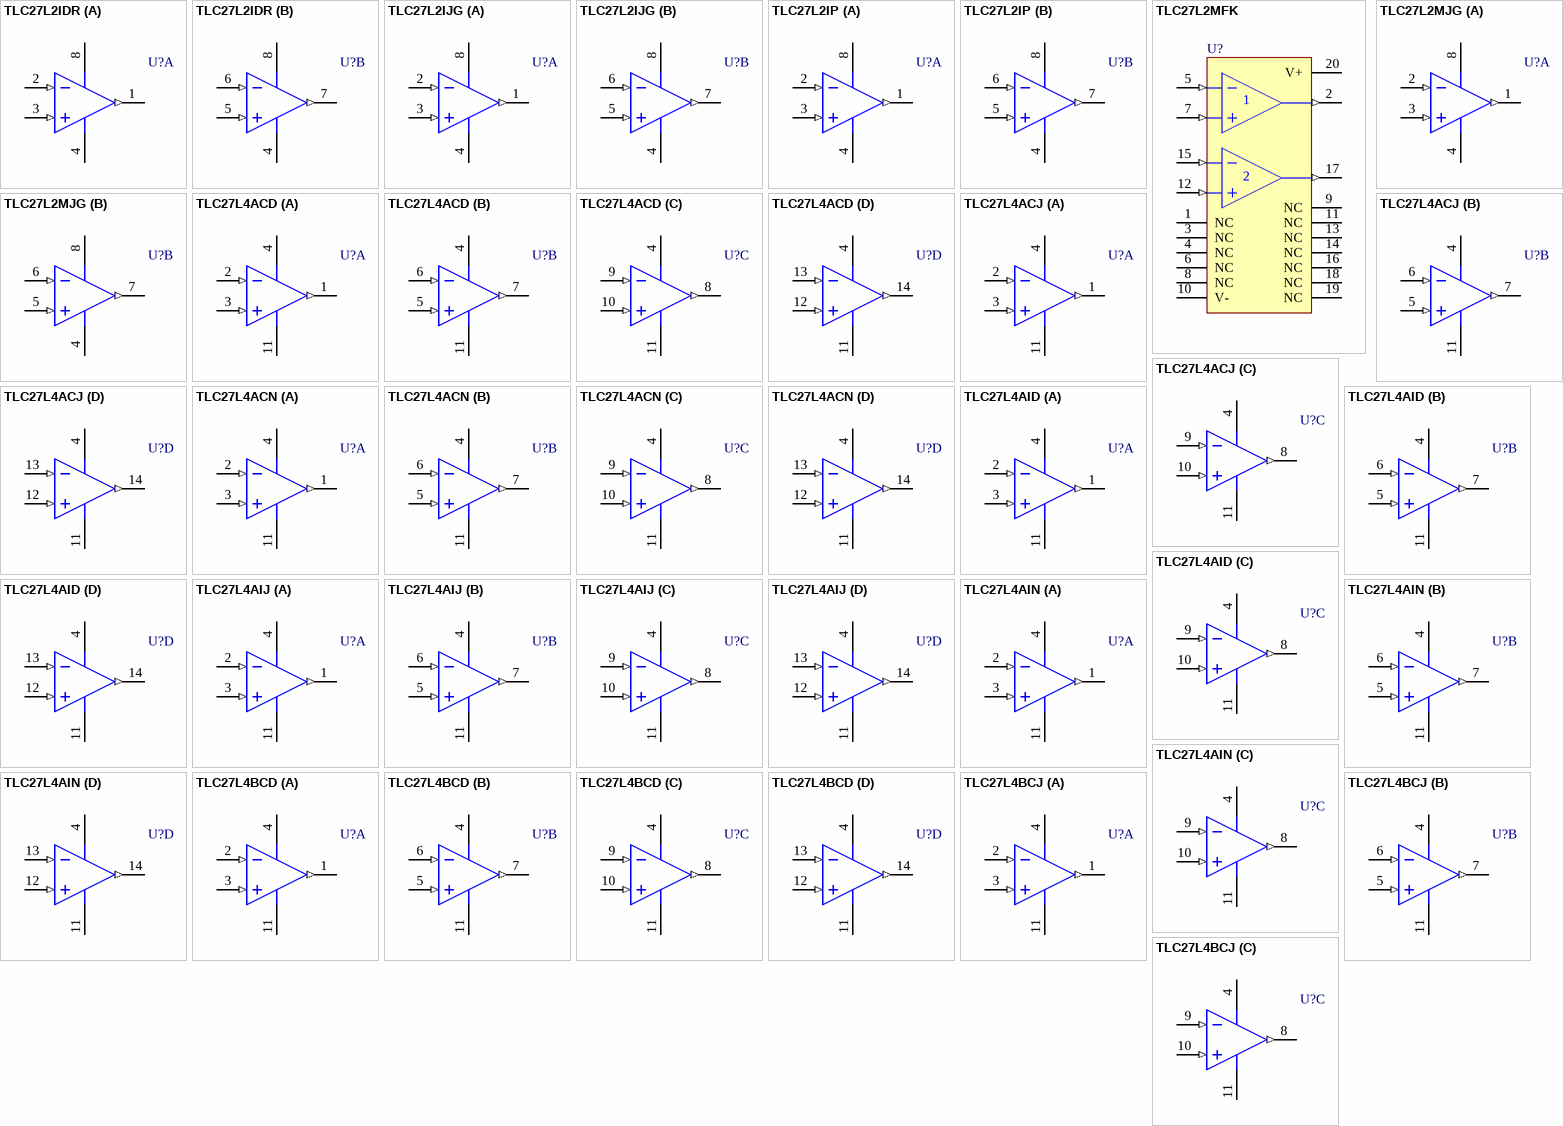
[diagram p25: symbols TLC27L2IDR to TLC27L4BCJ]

## TLC27L2IDR
designator U?
LinCMOS Precision Dual Operational Amplifier
footprint D008_L (SOIC, 8-Leads, Body 4.9x3.9mm, Pitch 1.27mm, IPC High Density)
footprint D008_M (SOIC, 8-Leads, Body 4.9x3.9mm, Pitch 1.27mm, IPC Low Density)
footprint D008_M (SOIC, 8-Leads, Body 4.9x3.9mm, Pitch 1.27mm, IPC Low Density)
3D model D008 (8-Pin Small Outline Integrated Circuit 1.27 mm Pitch)
pins on every part: 4 GND (power), 8 VDD (power)
part A pins: 1 OUT (out), 2 IN- (in), 3 IN+ (in)
part B pins: 5 IN+ (in), 6 IN- (in), 7 OUT (out)

## TLC27L2IJG
designator U?
LinCMOS Precision Dual Operational Amplifier
footprint JG008 (DIP; 8 Leads; Row Spacing 7.62 mm; Pitch 2.54 mm)
3D model JG008 (DIP; 8 Leads; Row Spacing 7.62 mm; Pitch 2.54 mm)
pins on every part: 4 GND (power), 8 VDD (power)
part A pins: 1 OUT (out), 2 IN- (in), 3 IN+ (in)
part B pins: 5 IN+ (in), 6 IN- (in), 7 OUT (out)

## TLC27L2IP
designator U?
LinCMOS Precision Dual Operational Amplifier
footprint P008 (DIP; 8 Leads; Row Spacing 7.62 mm; Pitch 2.54 mm)
3D model P008 (DIP; 8 Leads; Row Spacing 7.62 mm; Pitch 2.54 mm)
pins on every part: 4 GND (power), 8 VDD (power)
part A pins: 1 OUT (out), 2 IN- (in), 3 IN+ (in)
part B pins: 5 IN+ (in), 6 IN- (in), 7 OUT (out)

## TLC27L2MFK
designator U?
LinCMOS Precision Dual Operational Amplifier; ComponentAvailability: Obsolete
footprint FK020 (Leadless Chip Carrier; 20 Terminals; Body 8.9 x 8.9 mm)
pins: 1 NC, 2 OUT (out), 3 NC, 4 NC, 5 IN- (in), 6 NC, 7 IN+ (in), 8 NC, 9 NC, 10 V- (power), 11 NC, 12 IN+ (in), 13 NC, 14 NC, 15 IN- (in), 16 NC, 17 OUT (out), 18 NC, 19 NC, 20 V+ (power)

## TLC27L2MJG
designator U?
LinCMOS Precision Dual Operational Amplifier; ComponentAvailability: Obsolete
footprint JG008 (DIP; 8 Leads; Row Spacing 7.62 mm; Pitch 2.54 mm)
3D model JG008 (DIP; 8 Leads; Row Spacing 7.62 mm; Pitch 2.54 mm)
pins on every part: 4 GND (power), 8 VDD (power)
part A pins: 1 OUT (out), 2 IN- (in), 3 IN+ (in)
part B pins: 5 IN+ (in), 6 IN- (in), 7 OUT (out)

## TLC27L4ACD
designator U?
LinCMOS Precision Quad Operational Amplifier
footprint D014_N (SOIC, 14-Leads, Body 8.7x3.9mm, Pitch 1.27mm, IPC Medium Density)
footprint D014_L (SOIC, 14-Leads, Body 8.7x3.9mm, Pitch 1.27mm, IPC High Density)
footprint D014_M (SOIC, 14-Leads, Body 8.7x3.9mm, Pitch 1.27mm, IPC Low Density)
3D model D014 (14-Pin Small Outline Integrated Circuit 1.27 mm Pitch)
pins on every part: 4 V+ (power), 11 V- (power)
part A pins: 1 OUT (out), 2 IN- (in), 3 IN+ (in)
part B pins: 5 IN+ (in), 6 IN- (in), 7 OUT (out)
part C pins: 8 OUT (out), 9 IN- (in), 10 IN+ (in)
part D pins: 12 IN+ (in), 13 IN- (in), 14 OUT (out)

## TLC27L4ACJ
designator U?
LinCMOS Precision Quad Operational Amplifier
footprint J014 (DIP; 14 Leads; Row Spacing 7.62 mm; Pitch 2.54 mm)
3D model J014 (DIP; 14 Leads; Row Spacing 7.62 mm; Pitch 2.54 mm)
pins on every part: 4 V+ (power), 11 V- (power)
part A pins: 1 OUT (out), 2 IN- (in), 3 IN+ (in)
part B pins: 5 IN+ (in), 6 IN- (in), 7 OUT (out)
part C pins: 8 OUT (out), 9 IN- (in), 10 IN+ (in)
part D pins: 12 IN+ (in), 13 IN- (in), 14 OUT (out)

## TLC27L4ACN
designator U?
LinCMOS Precision Quad Operational Amplifier
footprint N014 (DIP; 14 Leads; Row Spacing 7.62 mm; Pitch 2.54 mm)
3D model N014 (DIP; 14 Leads; Row Spacing 7.62 mm; Pitch 2.54 mm)
pins on every part: 4 V+ (power), 11 V- (power)
part A pins: 1 OUT (out), 2 IN- (in), 3 IN+ (in)
part B pins: 5 IN+ (in), 6 IN- (in), 7 OUT (out)
part C pins: 8 OUT (out), 9 IN- (in), 10 IN+ (in)
part D pins: 12 IN+ (in), 13 IN- (in), 14 OUT (out)

## TLC27L4AID
designator U?
LinCMOS Precision Quad Operational Amplifier
footprint D014_N (SOIC, 14-Leads, Body 8.7x3.9mm, Pitch 1.27mm, IPC Medium Density)
footprint D014_L (SOIC, 14-Leads, Body 8.7x3.9mm, Pitch 1.27mm, IPC High Density)
footprint D014_M (SOIC, 14-Leads, Body 8.7x3.9mm, Pitch 1.27mm, IPC Low Density)
3D model D014 (14-Pin Small Outline Integrated Circuit 1.27 mm Pitch)
pins on every part: 4 V+ (power), 11 V- (power)
part A pins: 1 OUT (out), 2 IN- (in), 3 IN+ (in)
part B pins: 5 IN+ (in), 6 IN- (in), 7 OUT (out)
part C pins: 8 OUT (out), 9 IN- (in), 10 IN+ (in)
part D pins: 12 IN+ (in), 13 IN- (in), 14 OUT (out)

## TLC27L4AIJ
designator U?
LinCMOS Precision Quad Operational Amplifier
footprint J014 (DIP; 14 Leads; Row Spacing 7.62 mm; Pitch 2.54 mm)
3D model J014 (DIP; 14 Leads; Row Spacing 7.62 mm; Pitch 2.54 mm)
pins on every part: 4 V+ (power), 11 V- (power)
part A pins: 1 OUT (out), 2 IN- (in), 3 IN+ (in)
part B pins: 5 IN+ (in), 6 IN- (in), 7 OUT (out)
part C pins: 8 OUT (out), 9 IN- (in), 10 IN+ (in)
part D pins: 12 IN+ (in), 13 IN- (in), 14 OUT (out)

## TLC27L4AIN
designator U?
LinCMOS Precision Quad Operational Amplifier
footprint N014 (DIP; 14 Leads; Row Spacing 7.62 mm; Pitch 2.54 mm)
3D model N014 (DIP; 14 Leads; Row Spacing 7.62 mm; Pitch 2.54 mm)
pins on every part: 4 V+ (power), 11 V- (power)
part A pins: 1 OUT (out), 2 IN- (in), 3 IN+ (in)
part B pins: 5 IN+ (in), 6 IN- (in), 7 OUT (out)
part C pins: 8 OUT (out), 9 IN- (in), 10 IN+ (in)
part D pins: 12 IN+ (in), 13 IN- (in), 14 OUT (out)

## TLC27L4BCD
designator U?
LinCMOS Precision Quad Operational Amplifier
footprint D014_N (SOIC, 14-Leads, Body 8.7x3.9mm, Pitch 1.27mm, IPC Medium Density)
footprint D014_L (SOIC, 14-Leads, Body 8.7x3.9mm, Pitch 1.27mm, IPC High Density)
footprint D014_M (SOIC, 14-Leads, Body 8.7x3.9mm, Pitch 1.27mm, IPC Low Density)
3D model D014 (14-Pin Small Outline Integrated Circuit 1.27 mm Pitch)
pins on every part: 4 V+ (power), 11 V- (power)
part A pins: 1 OUT (out), 2 IN- (in), 3 IN+ (in)
part B pins: 5 IN+ (in), 6 IN- (in), 7 OUT (out)
part C pins: 8 OUT (out), 9 IN- (in), 10 IN+ (in)
part D pins: 12 IN+ (in), 13 IN- (in), 14 OUT (out)

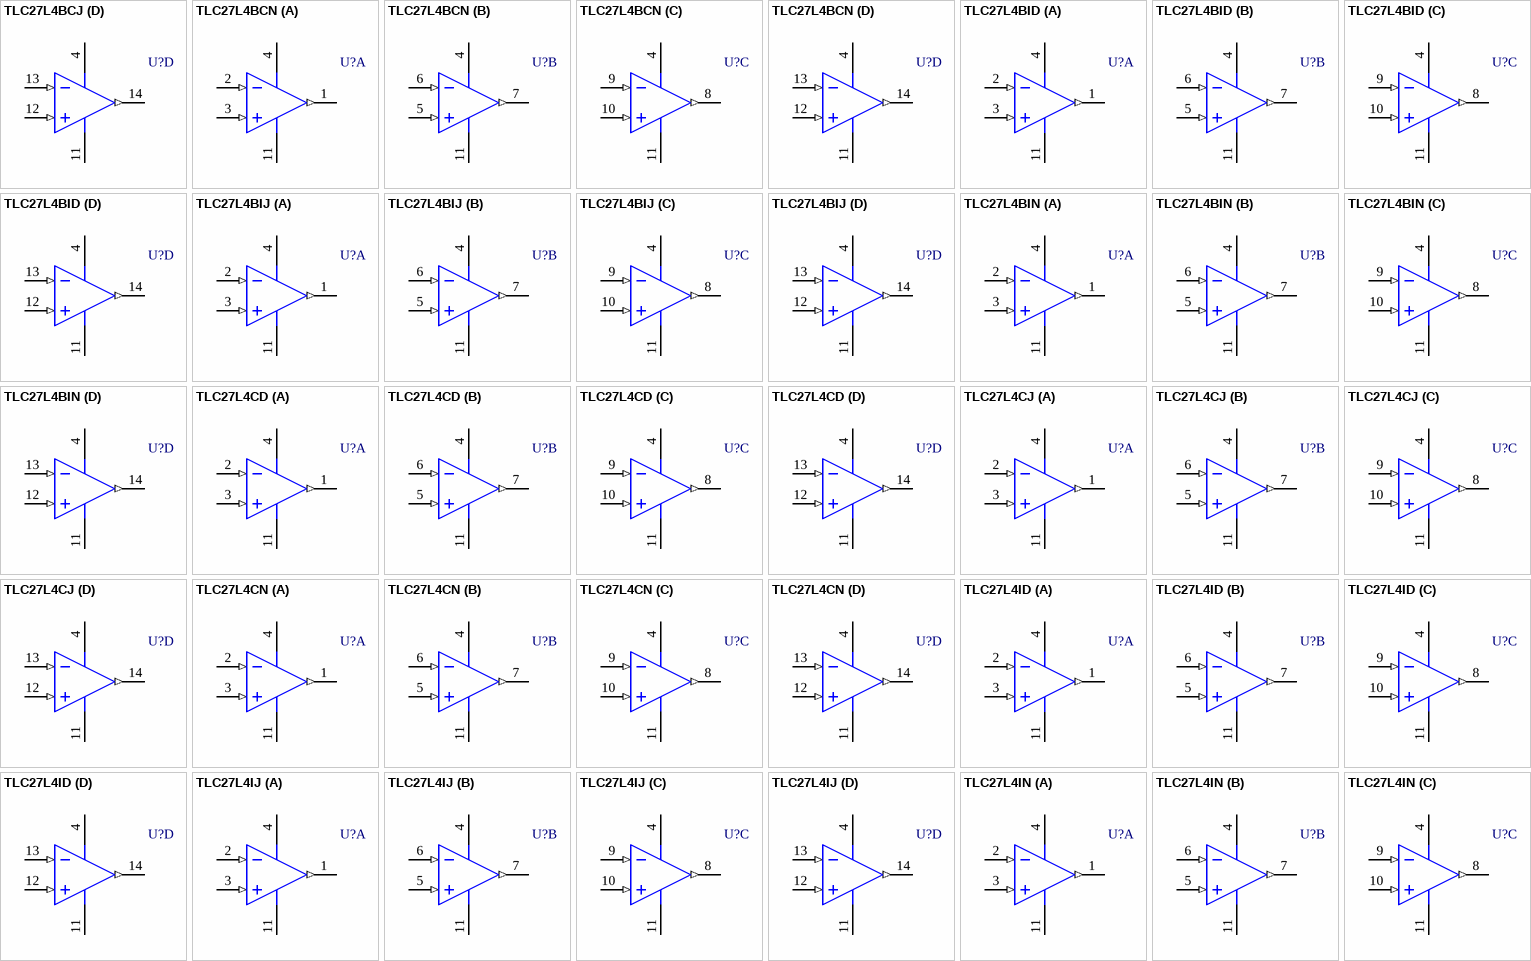
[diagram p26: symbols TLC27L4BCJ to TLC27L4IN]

## TLC27L4BCJ
designator U?
LinCMOS Precision Quad Operational Amplifier
footprint J014 (DIP; 14 Leads; Row Spacing 7.62 mm; Pitch 2.54 mm)
3D model J014 (DIP; 14 Leads; Row Spacing 7.62 mm; Pitch 2.54 mm)
pins on every part: 4 V+ (power), 11 V- (power)
part A pins: 1 OUT (out), 2 IN- (in), 3 IN+ (in)
part B pins: 5 IN+ (in), 6 IN- (in), 7 OUT (out)
part C pins: 8 OUT (out), 9 IN- (in), 10 IN+ (in)
part D pins: 12 IN+ (in), 13 IN- (in), 14 OUT (out)

## TLC27L4BCN
designator U?
LinCMOS Precision Quad Operational Amplifier
footprint N014 (DIP; 14 Leads; Row Spacing 7.62 mm; Pitch 2.54 mm)
3D model N014 (DIP; 14 Leads; Row Spacing 7.62 mm; Pitch 2.54 mm)
pins on every part: 4 V+ (power), 11 V- (power)
part A pins: 1 OUT (out), 2 IN- (in), 3 IN+ (in)
part B pins: 5 IN+ (in), 6 IN- (in), 7 OUT (out)
part C pins: 8 OUT (out), 9 IN- (in), 10 IN+ (in)
part D pins: 12 IN+ (in), 13 IN- (in), 14 OUT (out)

## TLC27L4BID
designator U?
LinCMOS Precision Quad Operational Amplifier
footprint D014_N (SOIC, 14-Leads, Body 8.7x3.9mm, Pitch 1.27mm, IPC Medium Density)
footprint D014_L (SOIC, 14-Leads, Body 8.7x3.9mm, Pitch 1.27mm, IPC High Density)
footprint D014_M (SOIC, 14-Leads, Body 8.7x3.9mm, Pitch 1.27mm, IPC Low Density)
3D model D014 (14-Pin Small Outline Integrated Circuit 1.27 mm Pitch)
pins on every part: 4 V+ (power), 11 V- (power)
part A pins: 1 OUT (out), 2 IN- (in), 3 IN+ (in)
part B pins: 5 IN+ (in), 6 IN- (in), 7 OUT (out)
part C pins: 8 OUT (out), 9 IN- (in), 10 IN+ (in)
part D pins: 12 IN+ (in), 13 IN- (in), 14 OUT (out)

## TLC27L4BIJ
designator U?
LinCMOS Precision Quad Operational Amplifier
footprint J014 (DIP; 14 Leads; Row Spacing 7.62 mm; Pitch 2.54 mm)
3D model J014 (DIP; 14 Leads; Row Spacing 7.62 mm; Pitch 2.54 mm)
pins on every part: 4 V+ (power), 11 V- (power)
part A pins: 1 OUT (out), 2 IN- (in), 3 IN+ (in)
part B pins: 5 IN+ (in), 6 IN- (in), 7 OUT (out)
part C pins: 8 OUT (out), 9 IN- (in), 10 IN+ (in)
part D pins: 12 IN+ (in), 13 IN- (in), 14 OUT (out)

## TLC27L4BIN
designator U?
LinCMOS Precision Quad Operational Amplifier
footprint N014 (DIP; 14 Leads; Row Spacing 7.62 mm; Pitch 2.54 mm)
3D model N014 (DIP; 14 Leads; Row Spacing 7.62 mm; Pitch 2.54 mm)
pins on every part: 4 V+ (power), 11 V- (power)
part A pins: 1 OUT (out), 2 IN- (in), 3 IN+ (in)
part B pins: 5 IN+ (in), 6 IN- (in), 7 OUT (out)
part C pins: 8 OUT (out), 9 IN- (in), 10 IN+ (in)
part D pins: 12 IN+ (in), 13 IN- (in), 14 OUT (out)

## TLC27L4CD
designator U?
LinCMOS Precision Quad Operational Amplifier
footprint D014_N (SOIC, 14-Leads, Body 8.7x3.9mm, Pitch 1.27mm, IPC Medium Density)
footprint D014_L (SOIC, 14-Leads, Body 8.7x3.9mm, Pitch 1.27mm, IPC High Density)
footprint D014_M (SOIC, 14-Leads, Body 8.7x3.9mm, Pitch 1.27mm, IPC Low Density)
3D model D014 (14-Pin Small Outline Integrated Circuit 1.27 mm Pitch)
pins on every part: 4 V+ (power), 11 V- (power)
part A pins: 1 OUT (out), 2 IN- (in), 3 IN+ (in)
part B pins: 5 IN+ (in), 6 IN- (in), 7 OUT (out)
part C pins: 8 OUT (out), 9 IN- (in), 10 IN+ (in)
part D pins: 12 IN+ (in), 13 IN- (in), 14 OUT (out)

## TLC27L4CJ
designator U?
LinCMOS Precision Quad Operational Amplifier
footprint J014 (DIP; 14 Leads; Row Spacing 7.62 mm; Pitch 2.54 mm)
3D model J014 (DIP; 14 Leads; Row Spacing 7.62 mm; Pitch 2.54 mm)
pins on every part: 4 V+ (power), 11 V- (power)
part A pins: 1 OUT (out), 2 IN- (in), 3 IN+ (in)
part B pins: 5 IN+ (in), 6 IN- (in), 7 OUT (out)
part C pins: 8 OUT (out), 9 IN- (in), 10 IN+ (in)
part D pins: 12 IN+ (in), 13 IN- (in), 14 OUT (out)

## TLC27L4CN
designator U?
LinCMOS Precision Quad Operational Amplifier
footprint N014 (DIP; 14 Leads; Row Spacing 7.62 mm; Pitch 2.54 mm)
3D model N014 (DIP; 14 Leads; Row Spacing 7.62 mm; Pitch 2.54 mm)
pins on every part: 4 V+ (power), 11 V- (power)
part A pins: 1 OUT (out), 2 IN- (in), 3 IN+ (in)
part B pins: 5 IN+ (in), 6 IN- (in), 7 OUT (out)
part C pins: 8 OUT (out), 9 IN- (in), 10 IN+ (in)
part D pins: 12 IN+ (in), 13 IN- (in), 14 OUT (out)

## TLC27L4ID
designator U?
LinCMOS Precision Quad Operational Amplifier
footprint D014_N (SOIC, 14-Leads, Body 8.7x3.9mm, Pitch 1.27mm, IPC Medium Density)
footprint D014_L (SOIC, 14-Leads, Body 8.7x3.9mm, Pitch 1.27mm, IPC High Density)
footprint D014_M (SOIC, 14-Leads, Body 8.7x3.9mm, Pitch 1.27mm, IPC Low Density)
3D model D014 (14-Pin Small Outline Integrated Circuit 1.27 mm Pitch)
pins on every part: 4 V+ (power), 11 V- (power)
part A pins: 1 OUT (out), 2 IN- (in), 3 IN+ (in)
part B pins: 5 IN+ (in), 6 IN- (in), 7 OUT (out)
part C pins: 8 OUT (out), 9 IN- (in), 10 IN+ (in)
part D pins: 12 IN+ (in), 13 IN- (in), 14 OUT (out)

## TLC27L4IJ
designator U?
LinCMOS Precision Quad Operational Amplifier
footprint J014 (DIP; 14 Leads; Row Spacing 7.62 mm; Pitch 2.54 mm)
3D model J014 (DIP; 14 Leads; Row Spacing 7.62 mm; Pitch 2.54 mm)
pins on every part: 4 V+ (power), 11 V- (power)
part A pins: 1 OUT (out), 2 IN- (in), 3 IN+ (in)
part B pins: 5 IN+ (in), 6 IN- (in), 7 OUT (out)
part C pins: 8 OUT (out), 9 IN- (in), 10 IN+ (in)
part D pins: 12 IN+ (in), 13 IN- (in), 14 OUT (out)

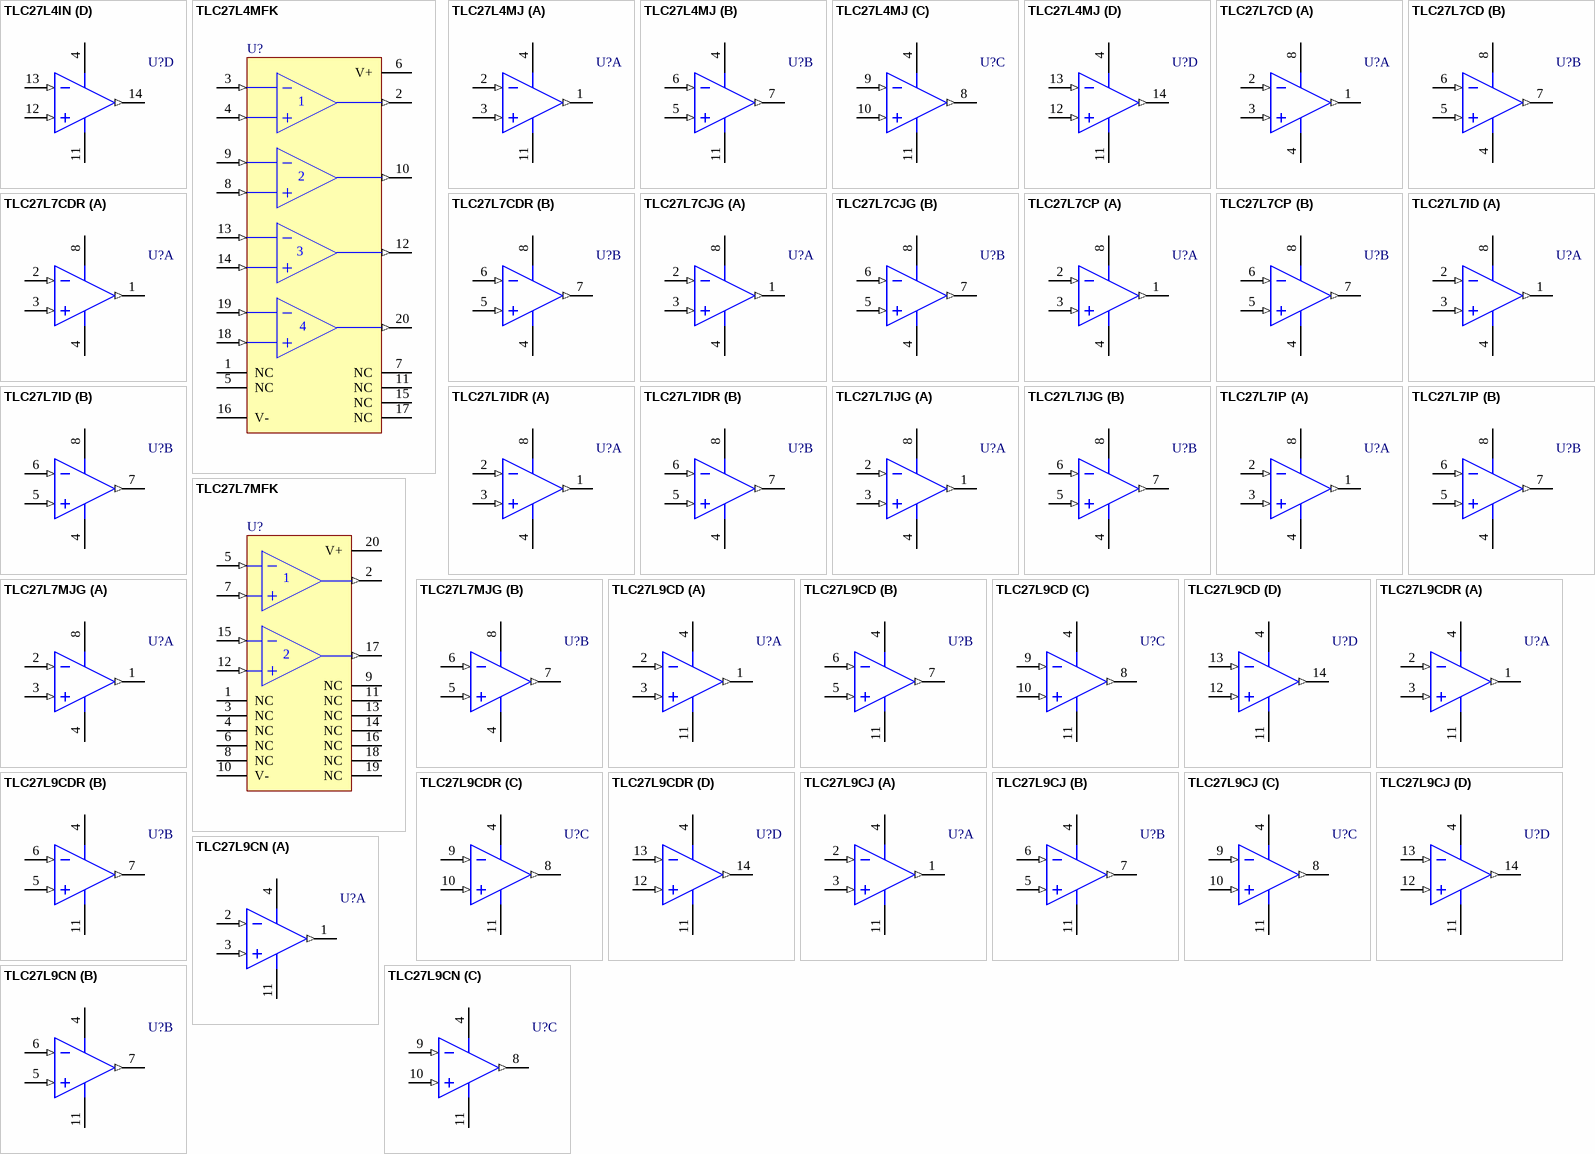
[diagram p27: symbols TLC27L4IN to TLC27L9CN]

## TLC27L4IN
designator U?
LinCMOS Precision Quad Operational Amplifier
footprint N014 (DIP; 14 Leads; Row Spacing 7.62 mm; Pitch 2.54 mm)
3D model N014 (DIP; 14 Leads; Row Spacing 7.62 mm; Pitch 2.54 mm)
pins on every part: 4 V+ (power), 11 V- (power)
part A pins: 1 OUT (out), 2 IN- (in), 3 IN+ (in)
part B pins: 5 IN+ (in), 6 IN- (in), 7 OUT (out)
part C pins: 8 OUT (out), 9 IN- (in), 10 IN+ (in)
part D pins: 12 IN+ (in), 13 IN- (in), 14 OUT (out)

## TLC27L4MFK
designator U?
LinCMOS Precision Quad Operational Amplifier; ComponentAvailability: Obsolete
footprint FK020 (Leadless Chip Carrier; 20 Terminals; Body 8.9 x 8.9 mm)
pins: 1 NC, 2 OUT (out), 3 IN- (in), 4 IN+ (in), 5 NC, 6 V+ (power), 7 NC, 8 IN+ (in), 9 IN- (in), 10 OUT (out), 11 NC, 12 OUT (out), 13 IN- (in), 14 IN+ (in), 15 NC, 16 V- (power), 17 NC, 18 IN+ (in), 19 IN- (in), 20 OUT (out)

## TLC27L4MJ
designator U?
LinCMOS Precision Quad Operational Amplifier; ComponentAvailability: Obsolete
footprint J014 (DIP; 14 Leads; Row Spacing 7.62 mm; Pitch 2.54 mm)
3D model J014 (DIP; 14 Leads; Row Spacing 7.62 mm; Pitch 2.54 mm)
pins on every part: 4 V+ (power), 11 V- (power)
part A pins: 1 OUT (out), 2 IN- (in), 3 IN+ (in)
part B pins: 5 IN+ (in), 6 IN- (in), 7 OUT (out)
part C pins: 8 OUT (out), 9 IN- (in), 10 IN+ (in)
part D pins: 12 IN+ (in), 13 IN- (in), 14 OUT (out)

## TLC27L7CD
designator U?
LinCMOS Precision Dual Operational Amplifier
footprint D008_L (SOIC, 8-Leads, Body 4.9x3.9mm, Pitch 1.27mm, IPC High Density)
footprint D008_M (SOIC, 8-Leads, Body 4.9x3.9mm, Pitch 1.27mm, IPC Low Density)
footprint D008_M (SOIC, 8-Leads, Body 4.9x3.9mm, Pitch 1.27mm, IPC Low Density)
3D model D008 (8-Pin Small Outline Integrated Circuit 1.27 mm Pitch)
pins on every part: 4 GND (power), 8 VDD (power)
part A pins: 1 OUT (out), 2 IN- (in), 3 IN+ (in)
part B pins: 5 IN+ (in), 6 IN- (in), 7 OUT (out)

## TLC27L7CDR
designator U?
LinCMOS Precision Dual Operational Amplifier
footprint D008_L (SOIC, 8-Leads, Body 4.9x3.9mm, Pitch 1.27mm, IPC High Density)
footprint D008_M (SOIC, 8-Leads, Body 4.9x3.9mm, Pitch 1.27mm, IPC Low Density)
footprint D008_M (SOIC, 8-Leads, Body 4.9x3.9mm, Pitch 1.27mm, IPC Low Density)
3D model D008 (8-Pin Small Outline Integrated Circuit 1.27 mm Pitch)
pins on every part: 4 GND (power), 8 VDD (power)
part A pins: 1 OUT (out), 2 IN- (in), 3 IN+ (in)
part B pins: 5 IN+ (in), 6 IN- (in), 7 OUT (out)

## TLC27L7CJG
designator U?
LinCMOS Precision Dual Operational Amplifier
footprint JG008 (DIP; 8 Leads; Row Spacing 7.62 mm; Pitch 2.54 mm)
3D model JG008 (DIP; 8 Leads; Row Spacing 7.62 mm; Pitch 2.54 mm)
pins on every part: 4 GND (power), 8 VDD (power)
part A pins: 1 OUT (out), 2 IN- (in), 3 IN+ (in)
part B pins: 5 IN+ (in), 6 IN- (in), 7 OUT (out)

## TLC27L7CP
designator U?
LinCMOS Precision Dual Operational Amplifier
footprint P008 (DIP; 8 Leads; Row Spacing 7.62 mm; Pitch 2.54 mm)
3D model P008 (DIP; 8 Leads; Row Spacing 7.62 mm; Pitch 2.54 mm)
pins on every part: 4 GND (power), 8 VDD (power)
part A pins: 1 OUT (out), 2 IN- (in), 3 IN+ (in)
part B pins: 5 IN+ (in), 6 IN- (in), 7 OUT (out)

## TLC27L7ID
designator U?
LinCMOS Precision Dual Operational Amplifier
footprint D008_L (SOIC, 8-Leads, Body 4.9x3.9mm, Pitch 1.27mm, IPC High Density)
footprint D008_M (SOIC, 8-Leads, Body 4.9x3.9mm, Pitch 1.27mm, IPC Low Density)
footprint D008_M (SOIC, 8-Leads, Body 4.9x3.9mm, Pitch 1.27mm, IPC Low Density)
3D model D008 (8-Pin Small Outline Integrated Circuit 1.27 mm Pitch)
pins on every part: 4 GND (power), 8 VDD (power)
part A pins: 1 OUT (out), 2 IN- (in), 3 IN+ (in)
part B pins: 5 IN+ (in), 6 IN- (in), 7 OUT (out)

## TLC27L7IDR
designator U?
LinCMOS Precision Dual Operational Amplifier
footprint D008_L (SOIC, 8-Leads, Body 4.9x3.9mm, Pitch 1.27mm, IPC High Density)
footprint D008_M (SOIC, 8-Leads, Body 4.9x3.9mm, Pitch 1.27mm, IPC Low Density)
footprint D008_M (SOIC, 8-Leads, Body 4.9x3.9mm, Pitch 1.27mm, IPC Low Density)
3D model D008 (8-Pin Small Outline Integrated Circuit 1.27 mm Pitch)
pins on every part: 4 GND (power), 8 VDD (power)
part A pins: 1 OUT (out), 2 IN- (in), 3 IN+ (in)
part B pins: 5 IN+ (in), 6 IN- (in), 7 OUT (out)

## TLC27L7IJG
designator U?
LinCMOS Precision Dual Operational Amplifier
footprint JG008 (DIP; 8 Leads; Row Spacing 7.62 mm; Pitch 2.54 mm)
3D model JG008 (DIP; 8 Leads; Row Spacing 7.62 mm; Pitch 2.54 mm)
pins on every part: 4 GND (power), 8 VDD (power)
part A pins: 1 OUT (out), 2 IN- (in), 3 IN+ (in)
part B pins: 5 IN+ (in), 6 IN- (in), 7 OUT (out)

## TLC27L7IP
designator U?
LinCMOS Precision Dual Operational Amplifier
footprint P008 (DIP; 8 Leads; Row Spacing 7.62 mm; Pitch 2.54 mm)
3D model P008 (DIP; 8 Leads; Row Spacing 7.62 mm; Pitch 2.54 mm)
pins on every part: 4 GND (power), 8 VDD (power)
part A pins: 1 OUT (out), 2 IN- (in), 3 IN+ (in)
part B pins: 5 IN+ (in), 6 IN- (in), 7 OUT (out)

## TLC27L7MFK
designator U?
LinCMOS Precision Dual Operational Amplifier; ComponentAvailability: Obsolete
footprint FK020 (Leadless Chip Carrier; 20 Terminals; Body 8.9 x 8.9 mm)
pins: 1 NC, 2 OUT (out), 3 NC, 4 NC, 5 IN- (in), 6 NC, 7 IN+ (in), 8 NC, 9 NC, 10 V- (power), 11 NC, 12 IN+ (in), 13 NC, 14 NC, 15 IN- (in), 16 NC, 17 OUT (out), 18 NC, 19 NC, 20 V+ (power)

## TLC27L7MJG
designator U?
LinCMOS Precision Dual Operational Amplifier; ComponentAvailability: Obsolete
footprint JG008 (DIP; 8 Leads; Row Spacing 7.62 mm; Pitch 2.54 mm)
3D model JG008 (DIP; 8 Leads; Row Spacing 7.62 mm; Pitch 2.54 mm)
pins on every part: 4 GND (power), 8 VDD (power)
part A pins: 1 OUT (out), 2 IN- (in), 3 IN+ (in)
part B pins: 5 IN+ (in), 6 IN- (in), 7 OUT (out)

## TLC27L9CD
designator U?
LinCMOS Precision Quad Operational Amplifier
footprint D014_N (SOIC, 14-Leads, Body 8.7x3.9mm, Pitch 1.27mm, IPC Medium Density)
footprint D014_L (SOIC, 14-Leads, Body 8.7x3.9mm, Pitch 1.27mm, IPC High Density)
footprint D014_M (SOIC, 14-Leads, Body 8.7x3.9mm, Pitch 1.27mm, IPC Low Density)
3D model D014 (14-Pin Small Outline Integrated Circuit 1.27 mm Pitch)
pins on every part: 4 V+ (power), 11 V- (power)
part A pins: 1 OUT (out), 2 IN- (in), 3 IN+ (in)
part B pins: 5 IN+ (in), 6 IN- (in), 7 OUT (out)
part C pins: 8 OUT (out), 9 IN- (in), 10 IN+ (in)
part D pins: 12 IN+ (in), 13 IN- (in), 14 OUT (out)

## TLC27L9CDR
designator U?
LinCMOS Precision Quad Operational Amplifier
footprint D014_N (SOIC, 14-Leads, Body 8.7x3.9mm, Pitch 1.27mm, IPC Medium Density)
footprint D014_L (SOIC, 14-Leads, Body 8.7x3.9mm, Pitch 1.27mm, IPC High Density)
footprint D014_M (SOIC, 14-Leads, Body 8.7x3.9mm, Pitch 1.27mm, IPC Low Density)
3D model D014 (14-Pin Small Outline Integrated Circuit 1.27 mm Pitch)
pins on every part: 4 V+ (power), 11 V- (power)
part A pins: 1 OUT (out), 2 IN- (in), 3 IN+ (in)
part B pins: 5 IN+ (in), 6 IN- (in), 7 OUT (out)
part C pins: 8 OUT (out), 9 IN- (in), 10 IN+ (in)
part D pins: 12 IN+ (in), 13 IN- (in), 14 OUT (out)

## TLC27L9CJ
designator U?
LinCMOS Precision Quad Operational Amplifier
footprint J014 (DIP; 14 Leads; Row Spacing 7.62 mm; Pitch 2.54 mm)
3D model J014 (DIP; 14 Leads; Row Spacing 7.62 mm; Pitch 2.54 mm)
pins on every part: 4 V+ (power), 11 V- (power)
part A pins: 1 OUT (out), 2 IN- (in), 3 IN+ (in)
part B pins: 5 IN+ (in), 6 IN- (in), 7 OUT (out)
part C pins: 8 OUT (out), 9 IN- (in), 10 IN+ (in)
part D pins: 12 IN+ (in), 13 IN- (in), 14 OUT (out)

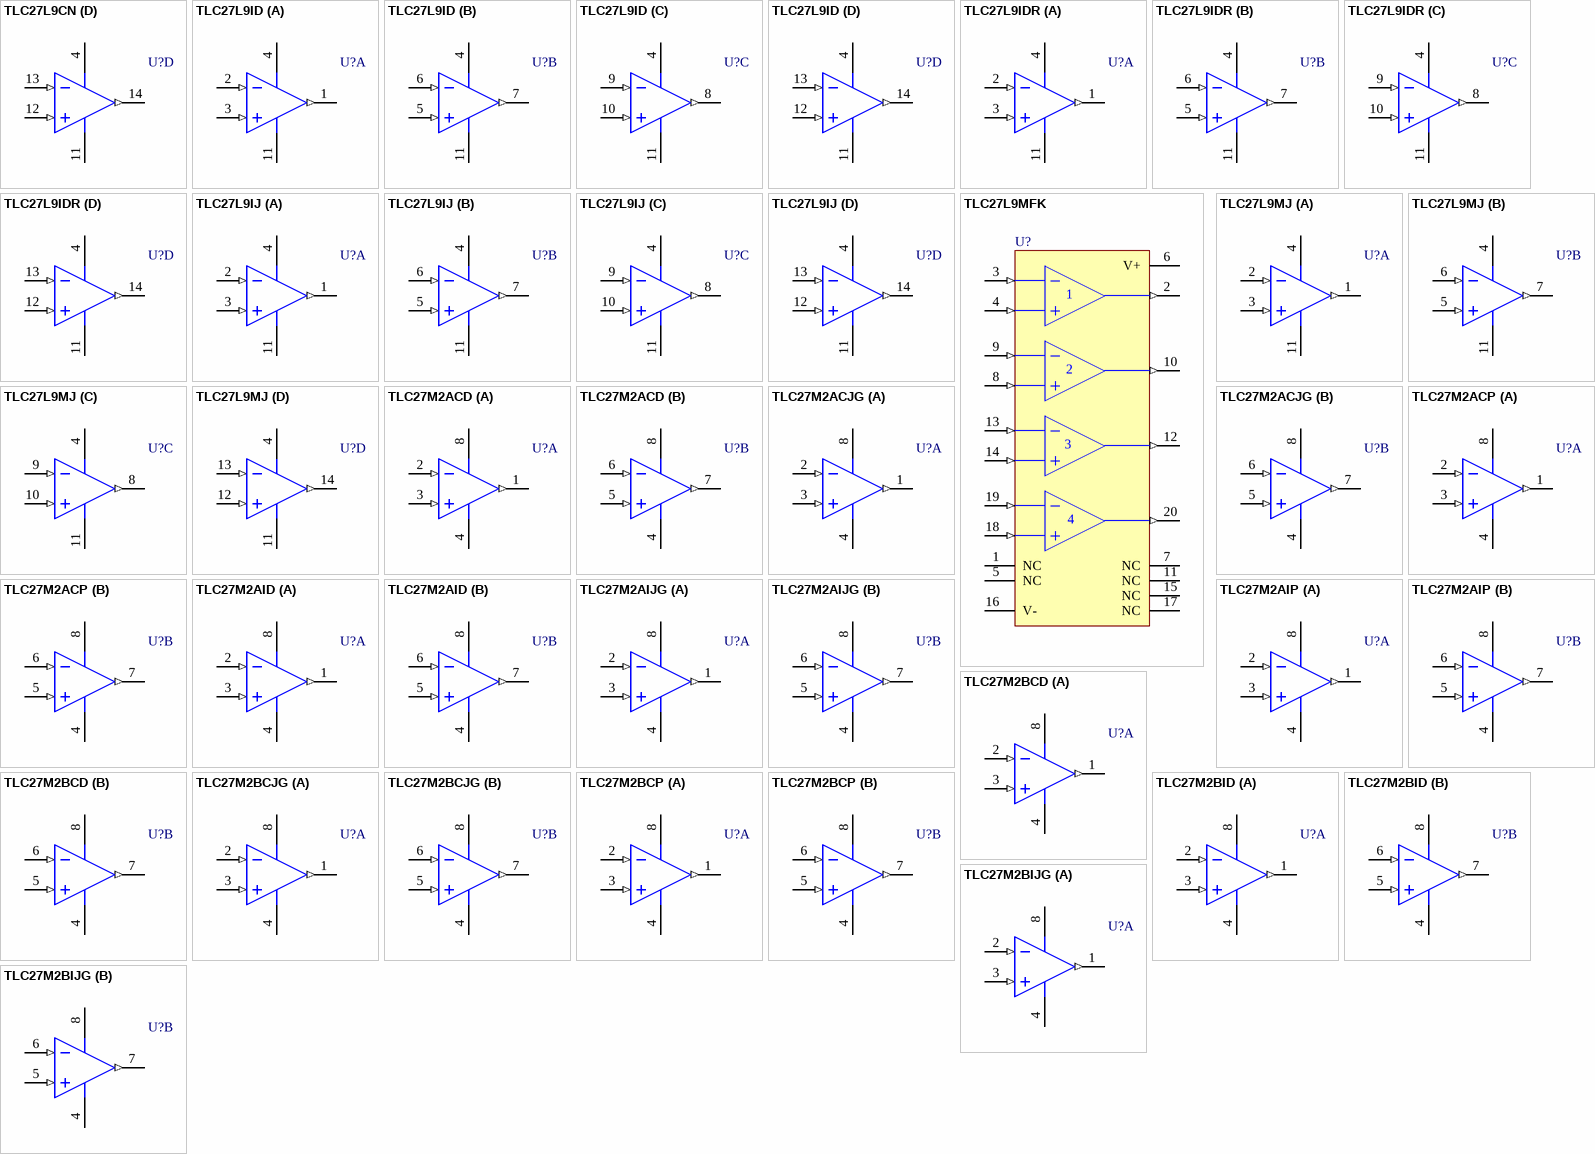
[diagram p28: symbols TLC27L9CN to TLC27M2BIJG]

## TLC27L9CN
designator U?
LinCMOS Precision Quad Operational Amplifier
footprint N014 (DIP; 14 Leads; Row Spacing 7.62 mm; Pitch 2.54 mm)
3D model N014 (DIP; 14 Leads; Row Spacing 7.62 mm; Pitch 2.54 mm)
pins on every part: 4 V+ (power), 11 V- (power)
part A pins: 1 OUT (out), 2 IN- (in), 3 IN+ (in)
part B pins: 5 IN+ (in), 6 IN- (in), 7 OUT (out)
part C pins: 8 OUT (out), 9 IN- (in), 10 IN+ (in)
part D pins: 12 IN+ (in), 13 IN- (in), 14 OUT (out)

## TLC27L9ID
designator U?
LinCMOS Precision Quad Operational Amplifier
footprint D014_N (SOIC, 14-Leads, Body 8.7x3.9mm, Pitch 1.27mm, IPC Medium Density)
footprint D014_L (SOIC, 14-Leads, Body 8.7x3.9mm, Pitch 1.27mm, IPC High Density)
footprint D014_M (SOIC, 14-Leads, Body 8.7x3.9mm, Pitch 1.27mm, IPC Low Density)
3D model D014 (14-Pin Small Outline Integrated Circuit 1.27 mm Pitch)
pins on every part: 4 V+ (power), 11 V- (power)
part A pins: 1 OUT (out), 2 IN- (in), 3 IN+ (in)
part B pins: 5 IN+ (in), 6 IN- (in), 7 OUT (out)
part C pins: 8 OUT (out), 9 IN- (in), 10 IN+ (in)
part D pins: 12 IN+ (in), 13 IN- (in), 14 OUT (out)

## TLC27L9IDR
designator U?
LinCMOS Precision Quad Operational Amplifier
footprint D014_N (SOIC, 14-Leads, Body 8.7x3.9mm, Pitch 1.27mm, IPC Medium Density)
footprint D014_L (SOIC, 14-Leads, Body 8.7x3.9mm, Pitch 1.27mm, IPC High Density)
footprint D014_M (SOIC, 14-Leads, Body 8.7x3.9mm, Pitch 1.27mm, IPC Low Density)
3D model D014 (14-Pin Small Outline Integrated Circuit 1.27 mm Pitch)
pins on every part: 4 V+ (power), 11 V- (power)
part A pins: 1 OUT (out), 2 IN- (in), 3 IN+ (in)
part B pins: 5 IN+ (in), 6 IN- (in), 7 OUT (out)
part C pins: 8 OUT (out), 9 IN- (in), 10 IN+ (in)
part D pins: 12 IN+ (in), 13 IN- (in), 14 OUT (out)

## TLC27L9IJ
designator U?
LinCMOS Precision Quad Operational Amplifier
footprint J014 (DIP; 14 Leads; Row Spacing 7.62 mm; Pitch 2.54 mm)
3D model J014 (DIP; 14 Leads; Row Spacing 7.62 mm; Pitch 2.54 mm)
pins on every part: 4 V+ (power), 11 V- (power)
part A pins: 1 OUT (out), 2 IN- (in), 3 IN+ (in)
part B pins: 5 IN+ (in), 6 IN- (in), 7 OUT (out)
part C pins: 8 OUT (out), 9 IN- (in), 10 IN+ (in)
part D pins: 12 IN+ (in), 13 IN- (in), 14 OUT (out)

## TLC27L9MFK
designator U?
LinCMOS Precision Quad Operational Amplifier; ComponentAvailability: Obsolete
footprint FK020 (Leadless Chip Carrier; 20 Terminals; Body 8.9 x 8.9 mm)
pins: 1 NC, 2 OUT (out), 3 IN- (in), 4 IN+ (in), 5 NC, 6 V+ (power), 7 NC, 8 IN+ (in), 9 IN- (in), 10 OUT (out), 11 NC, 12 OUT (out), 13 IN- (in), 14 IN+ (in), 15 NC, 16 V- (power), 17 NC, 18 IN+ (in), 19 IN- (in), 20 OUT (out)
